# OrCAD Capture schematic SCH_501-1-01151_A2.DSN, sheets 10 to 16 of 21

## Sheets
10 P10_IMX CONTROL: size A3
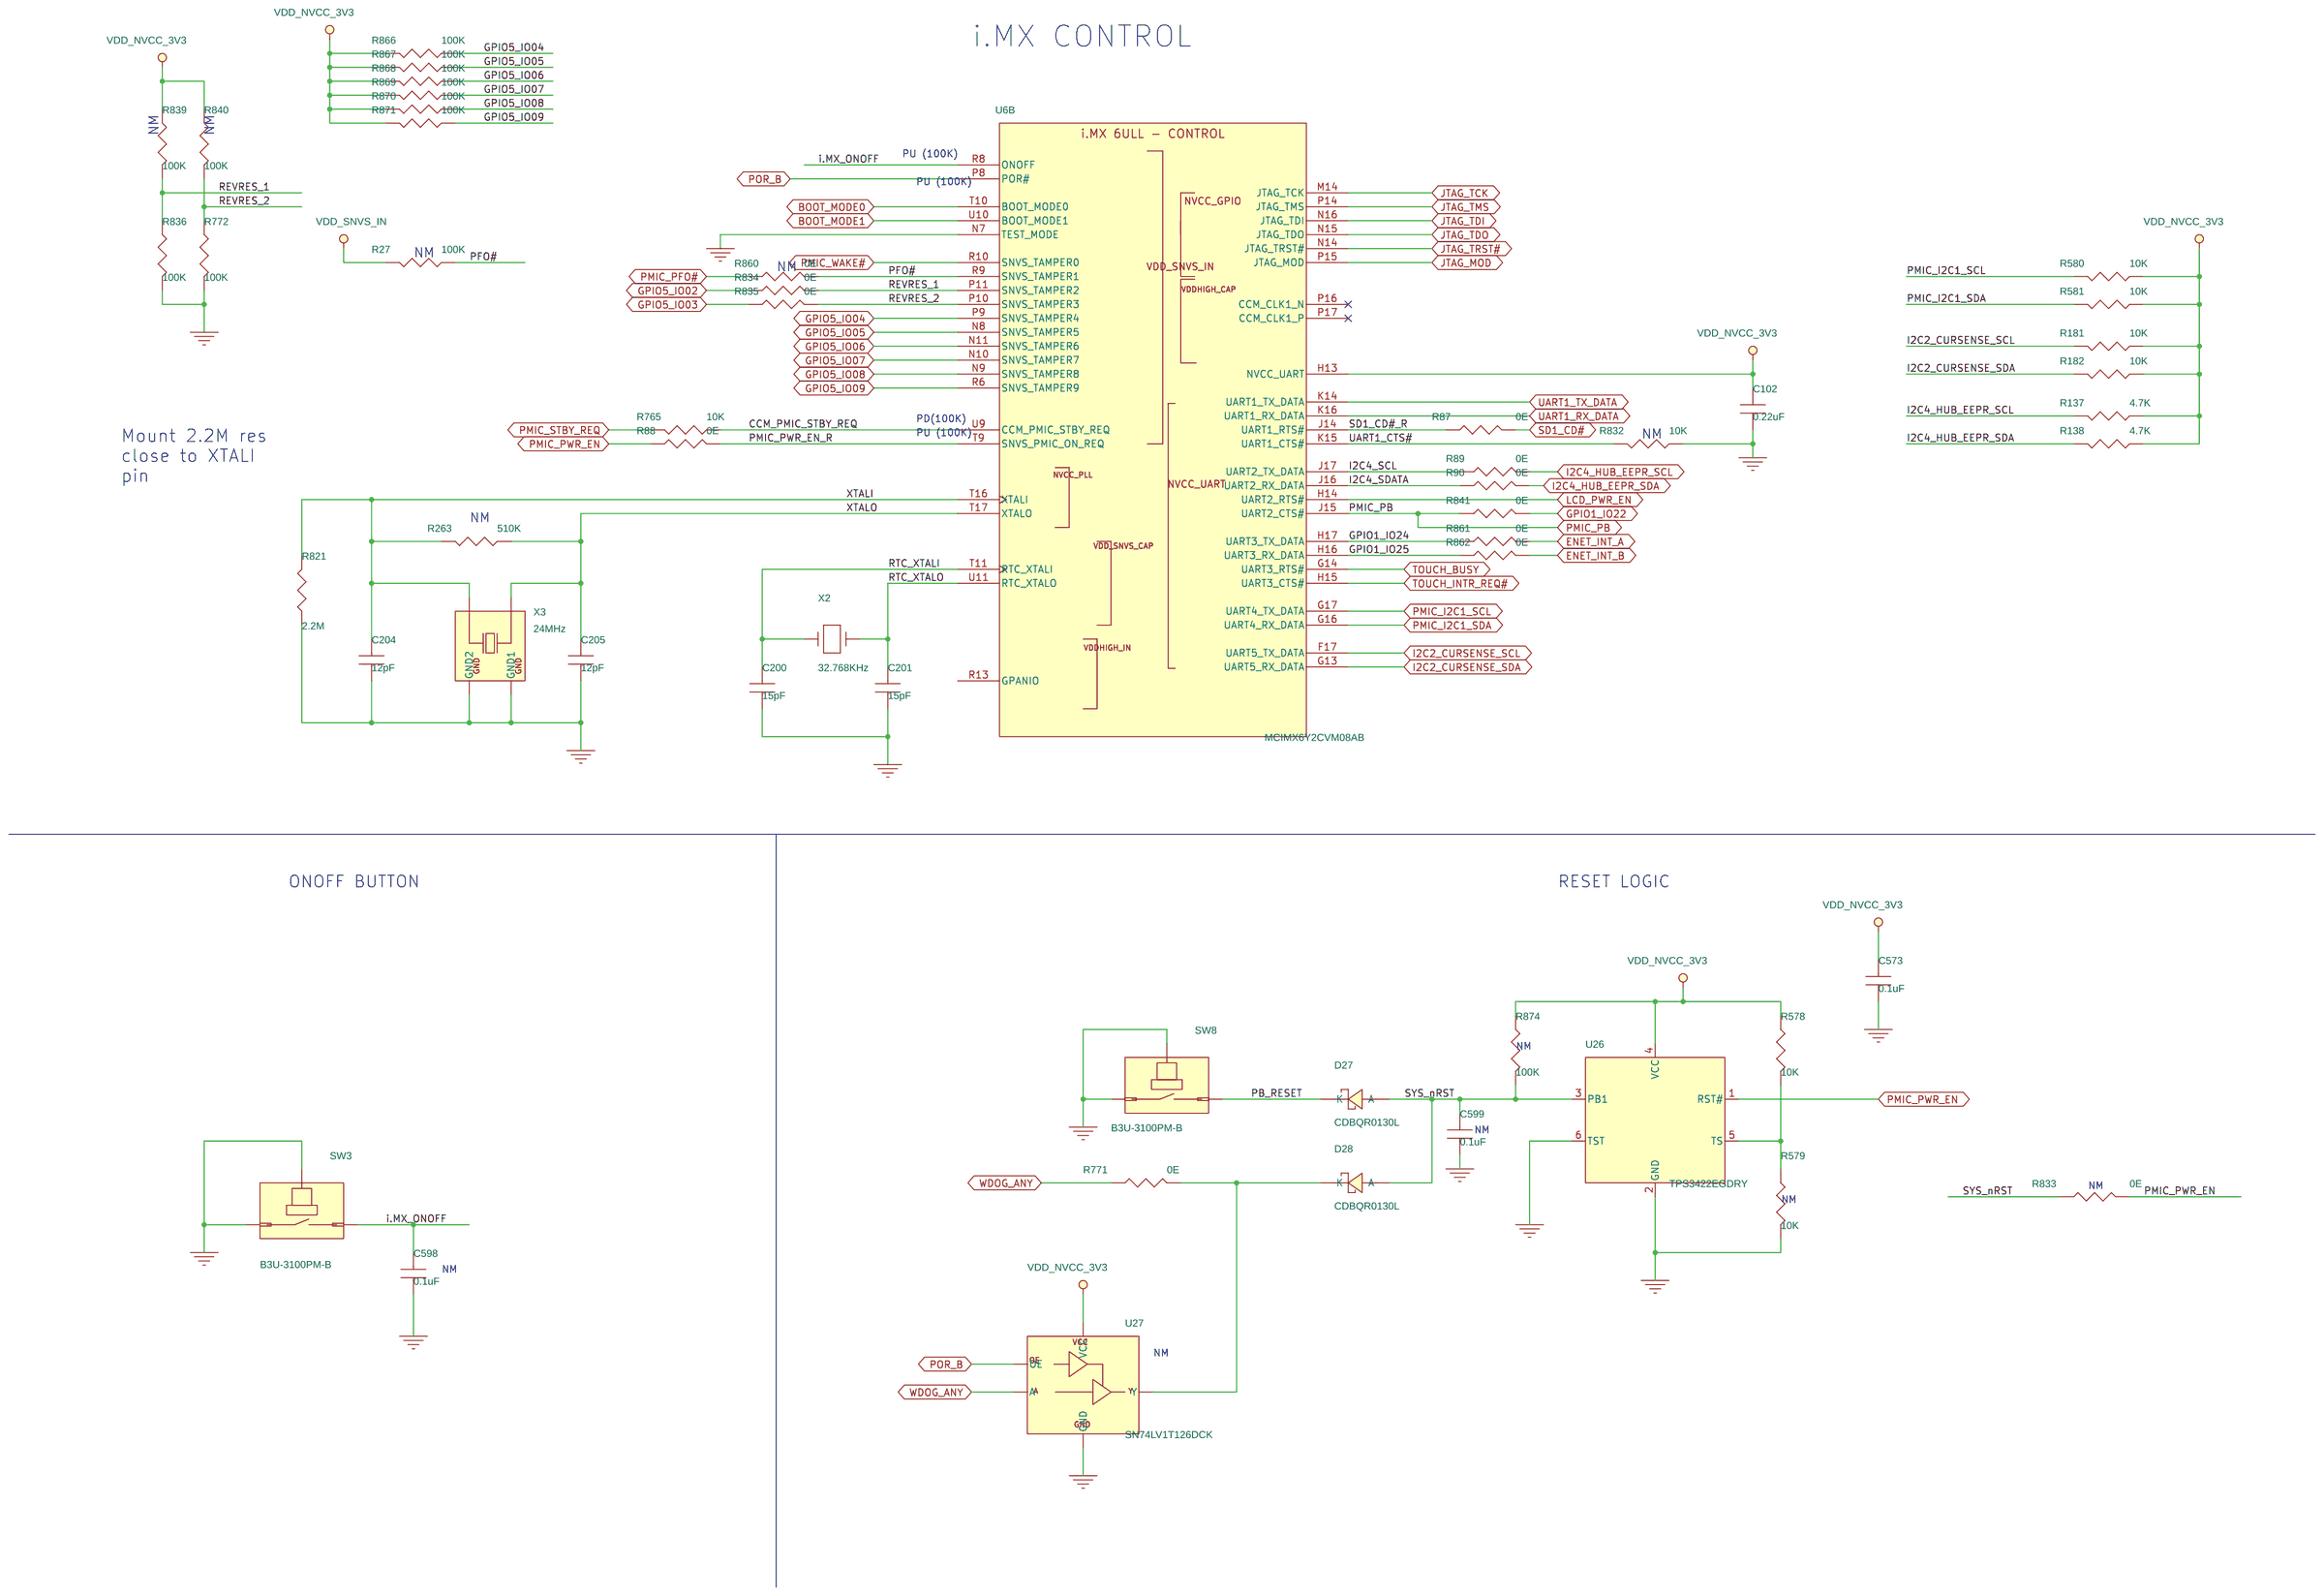
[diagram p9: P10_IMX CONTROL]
11 P11_eMMC: size A3
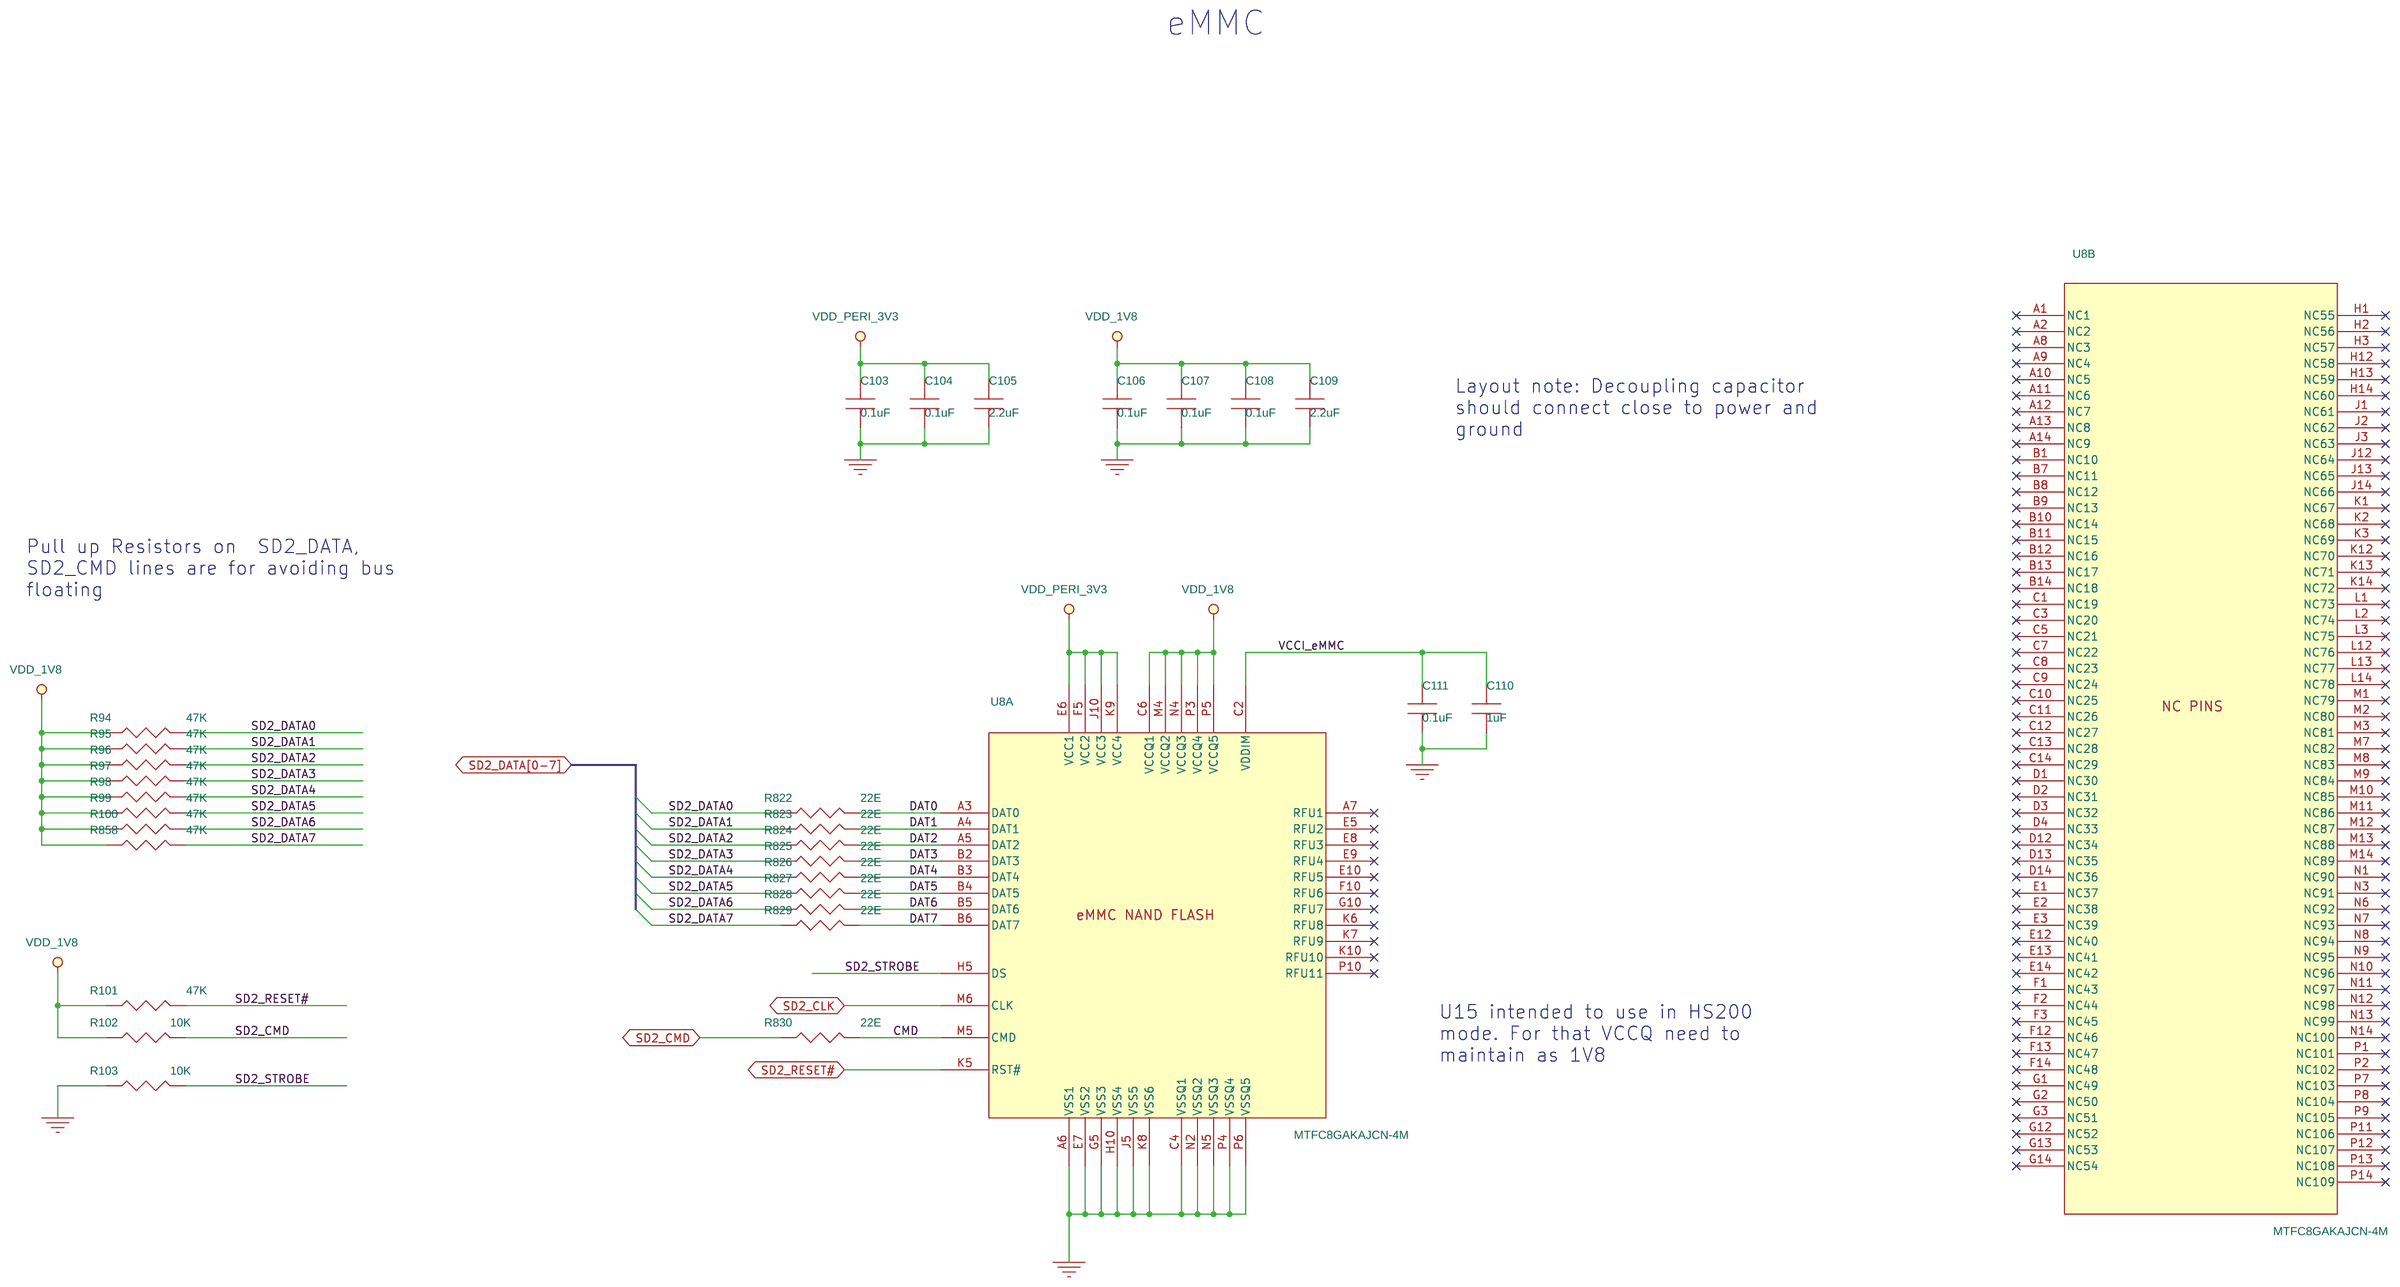
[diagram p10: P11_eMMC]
12 P12_NOR FLASH_SD CARD: size A3
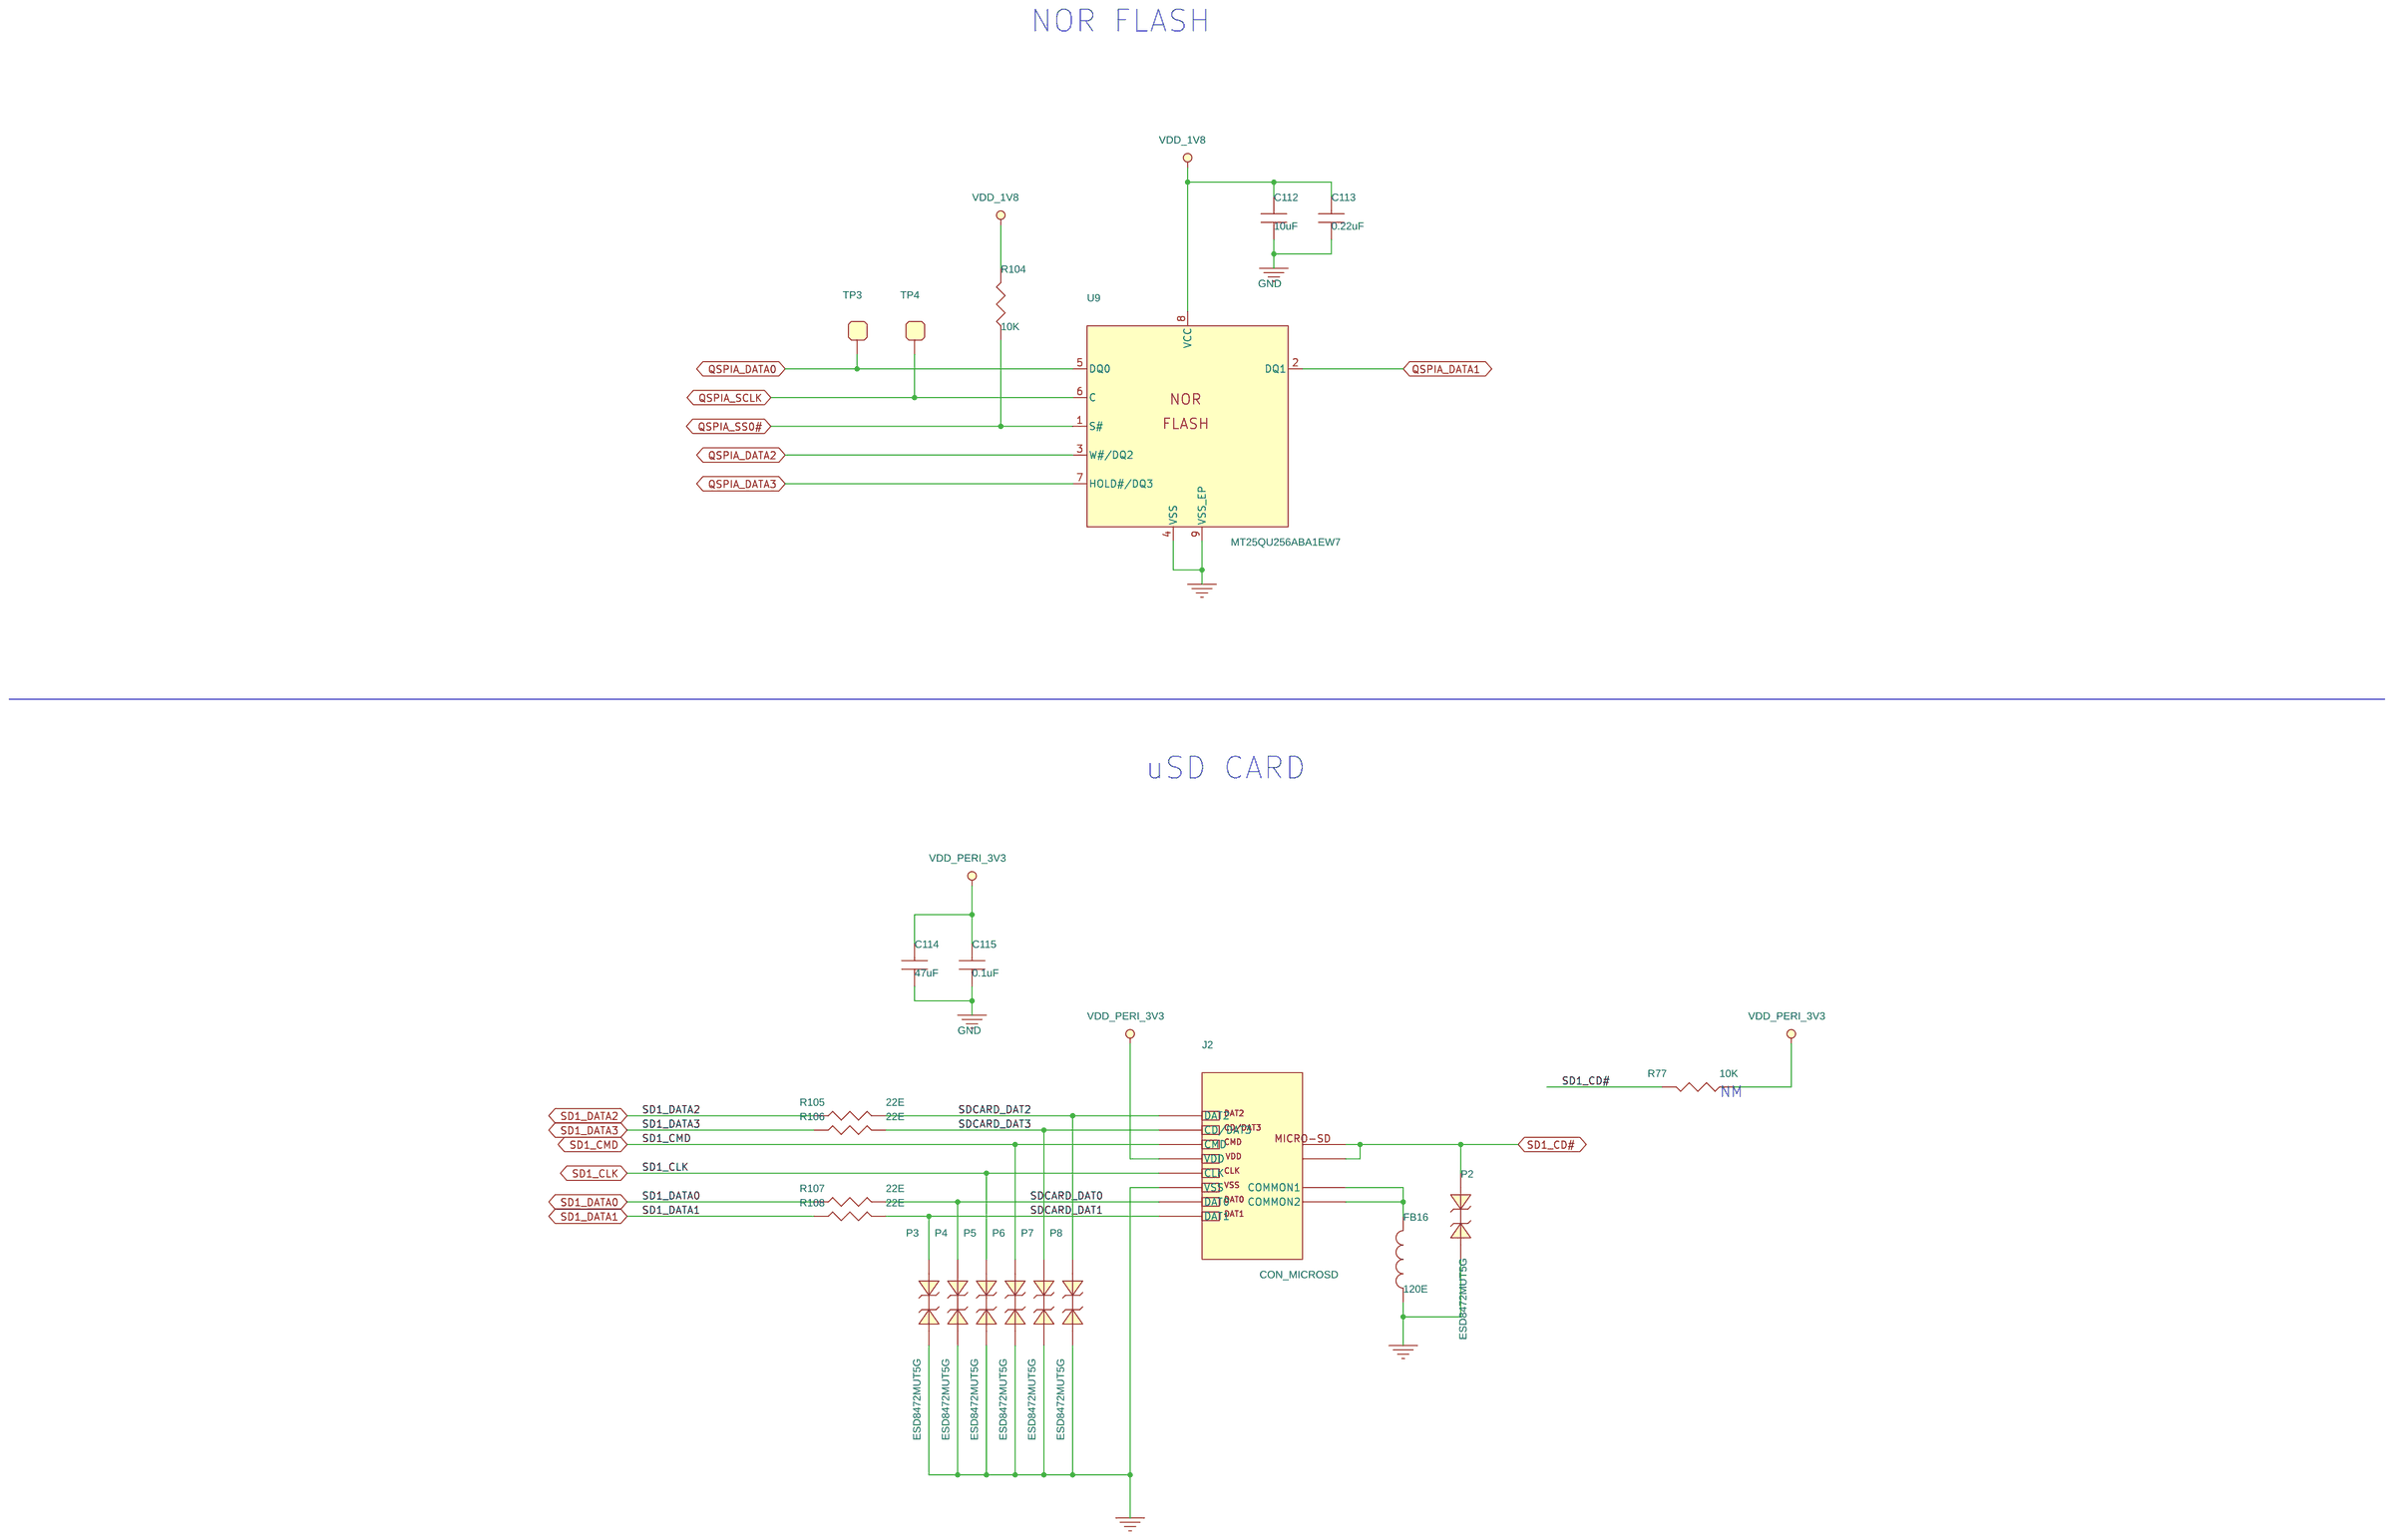
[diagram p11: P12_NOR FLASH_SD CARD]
13 P13_ETHERNET PHY: size A3
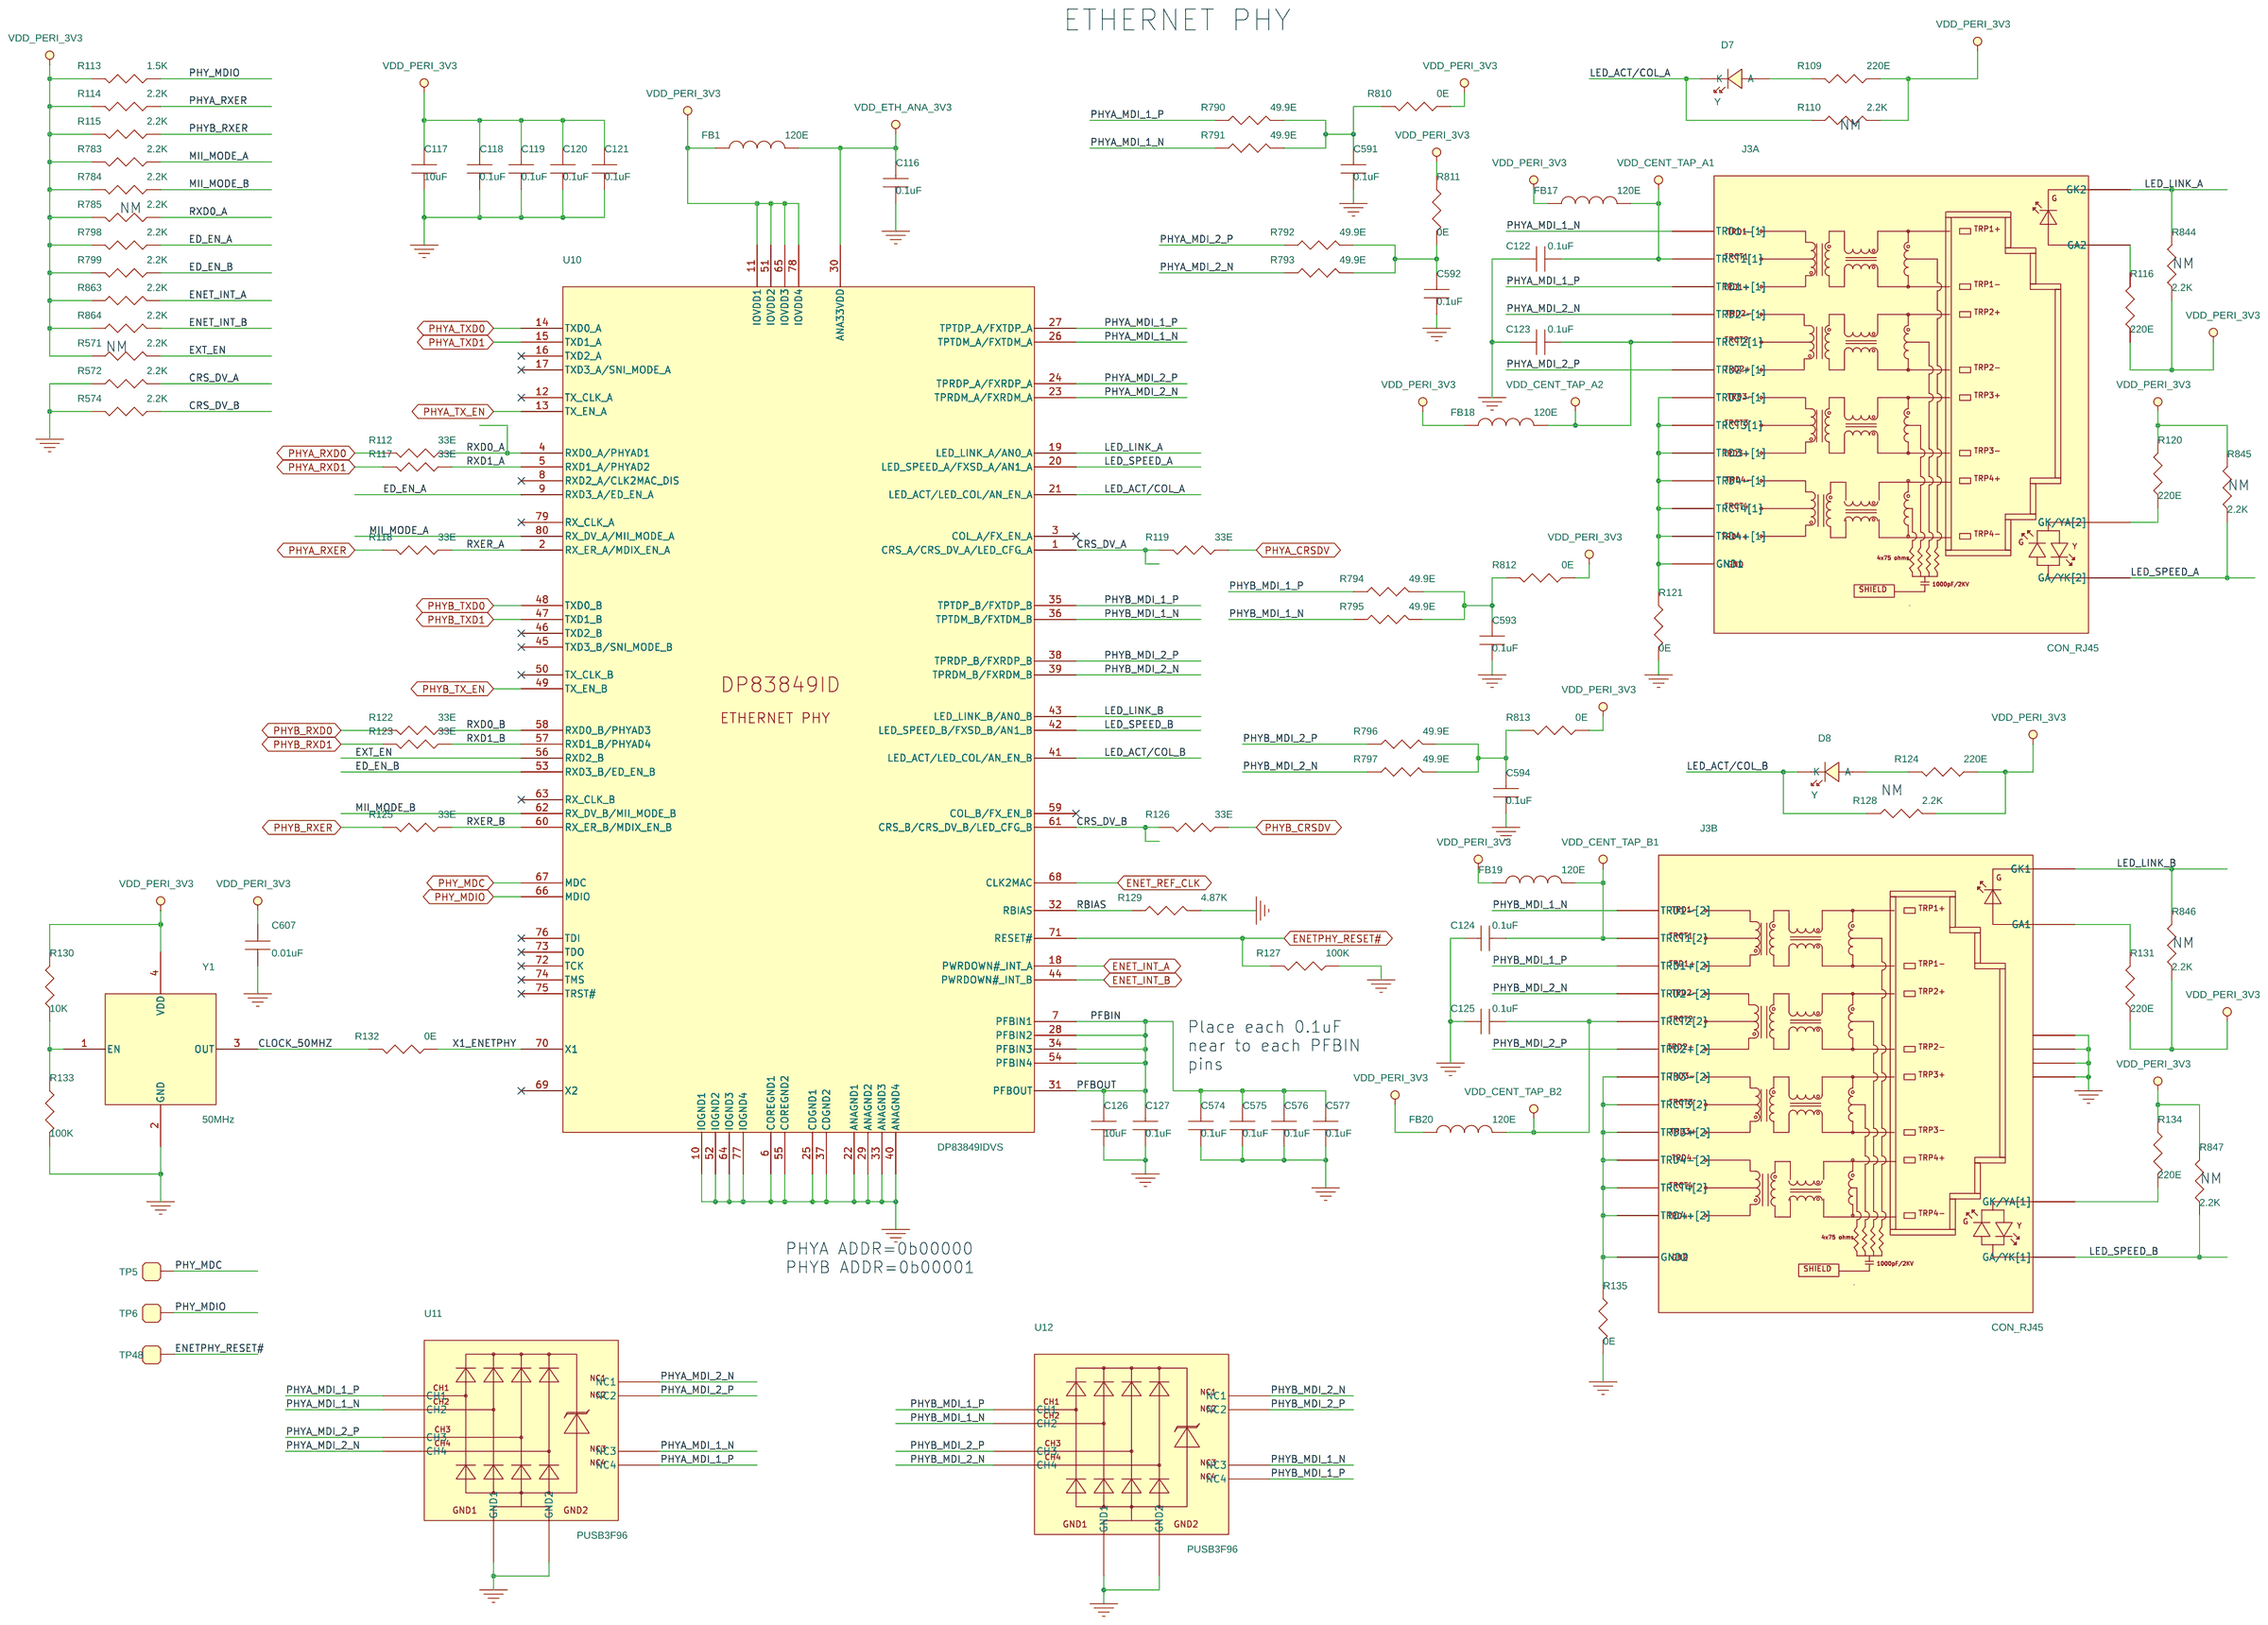
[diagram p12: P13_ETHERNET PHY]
14 P14_USB HUB: size A3
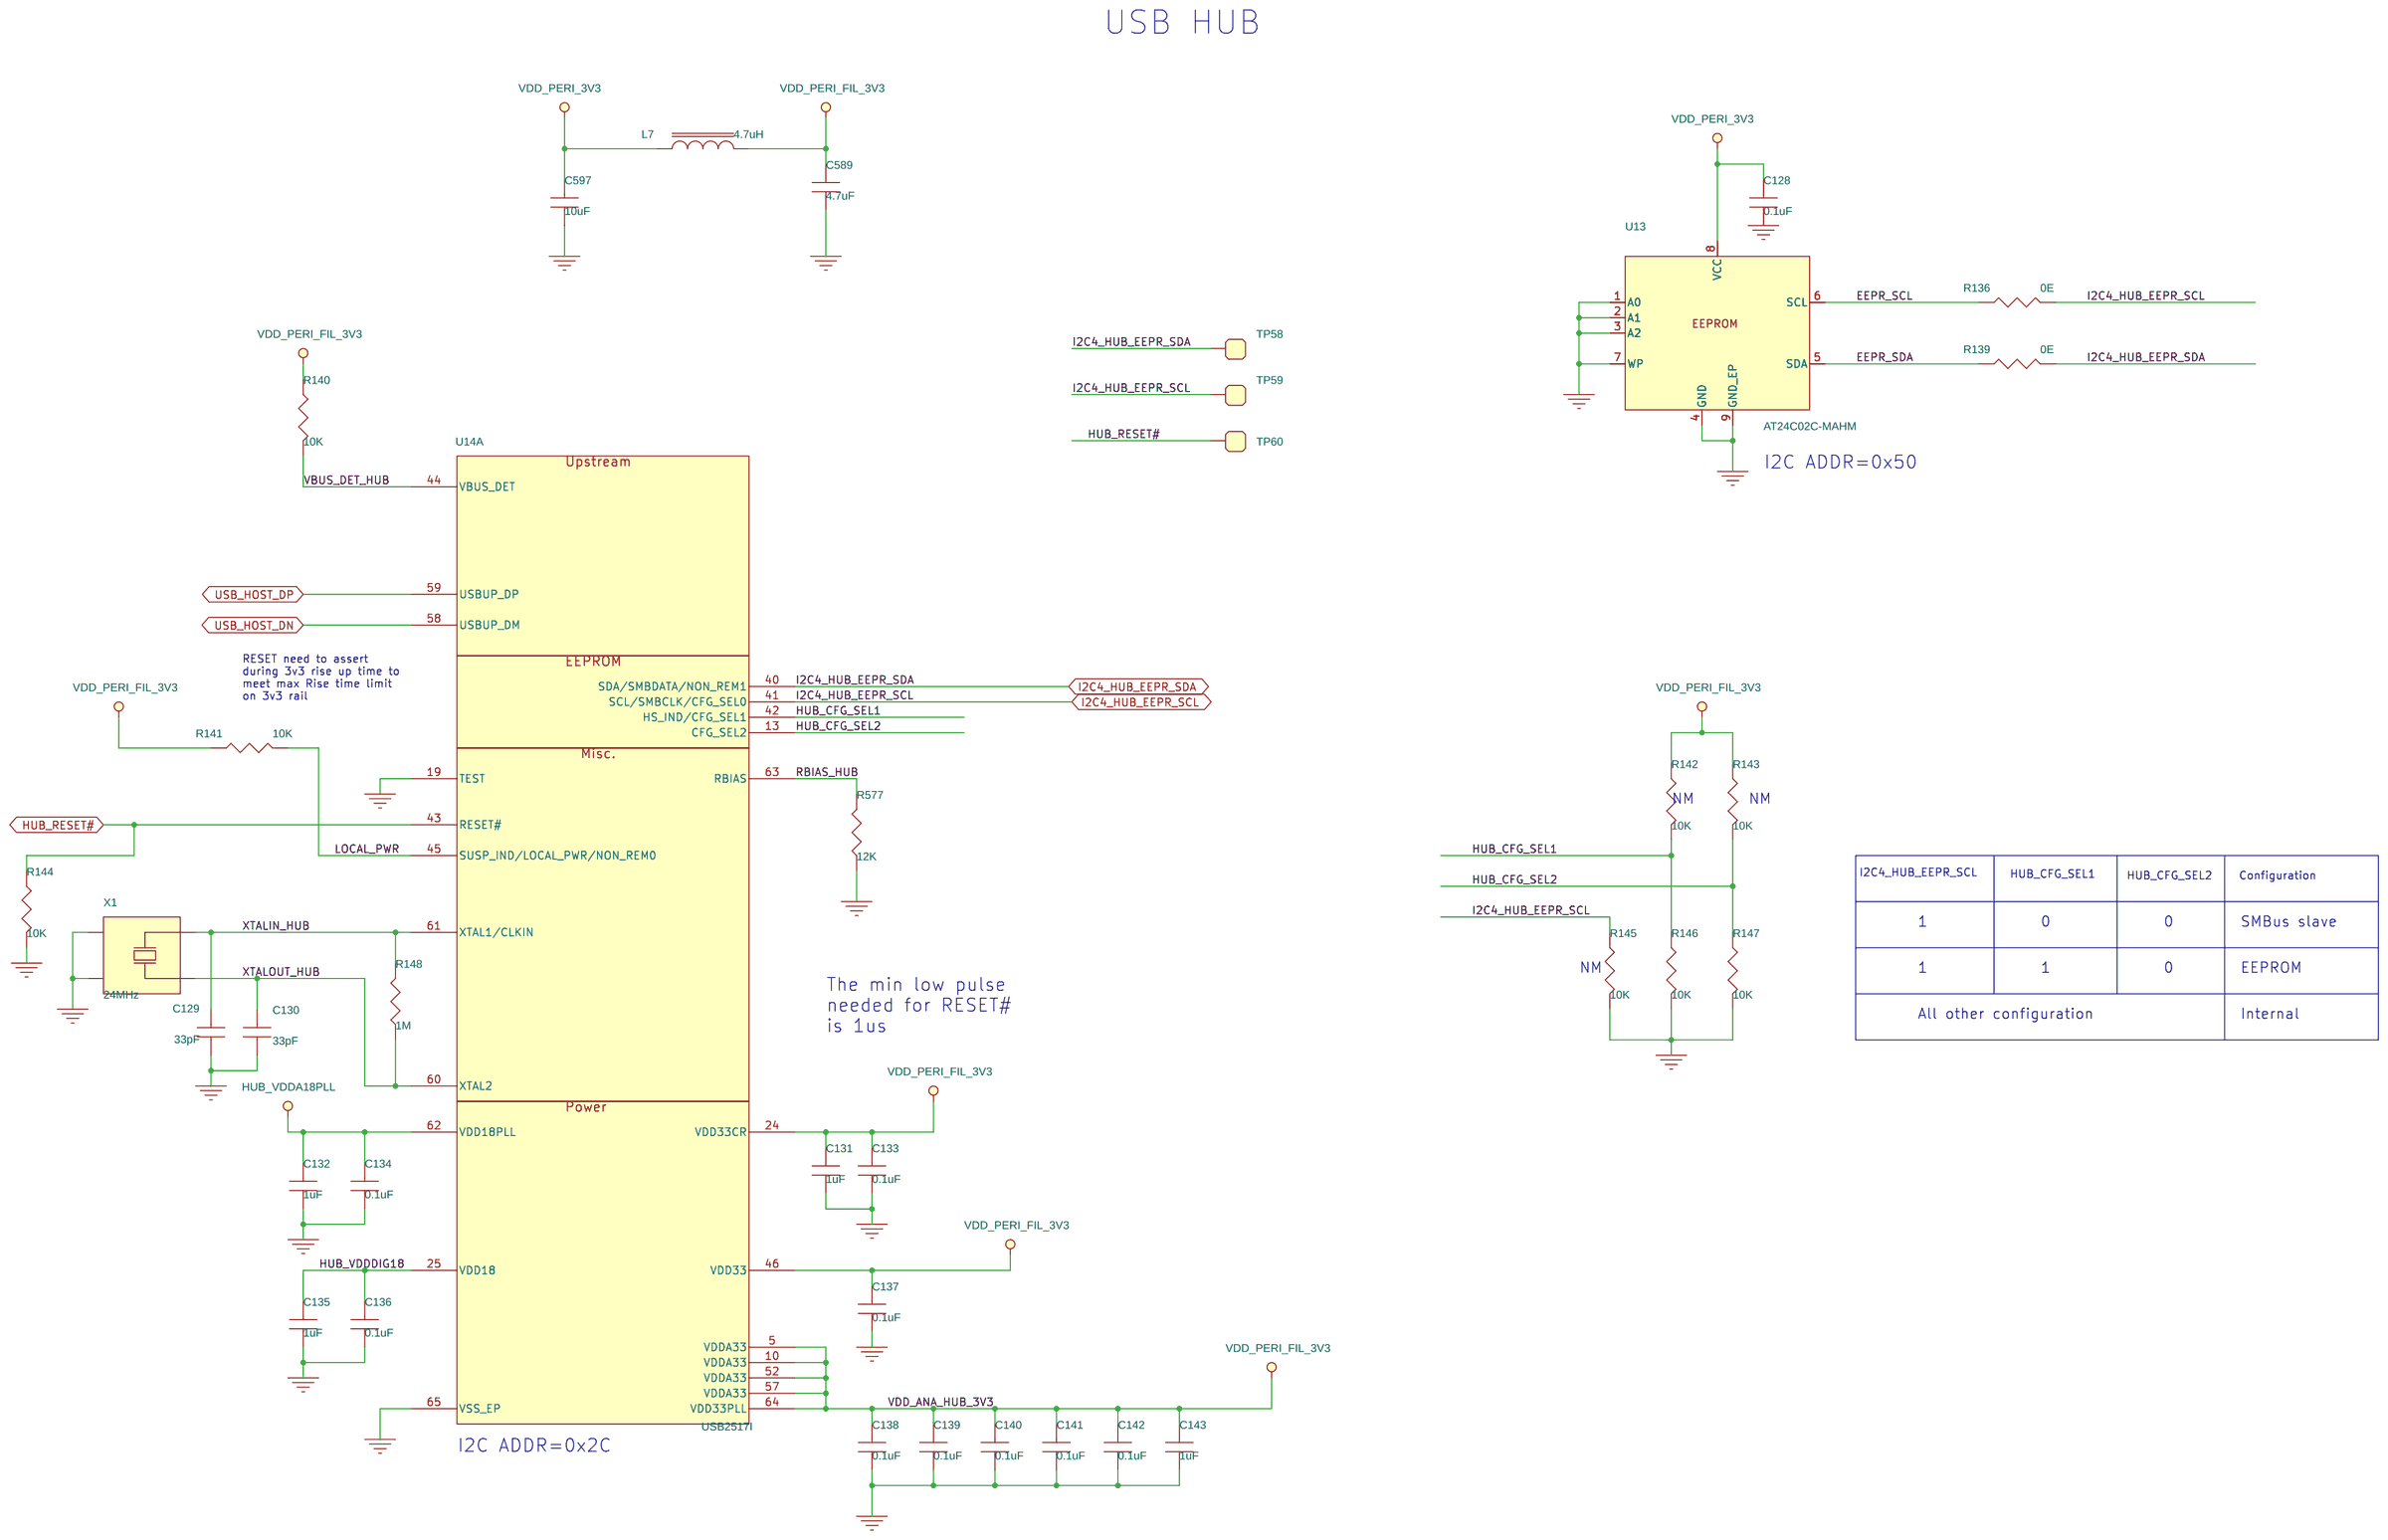
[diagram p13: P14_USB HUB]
15 P16_USB HUB CON: size A3
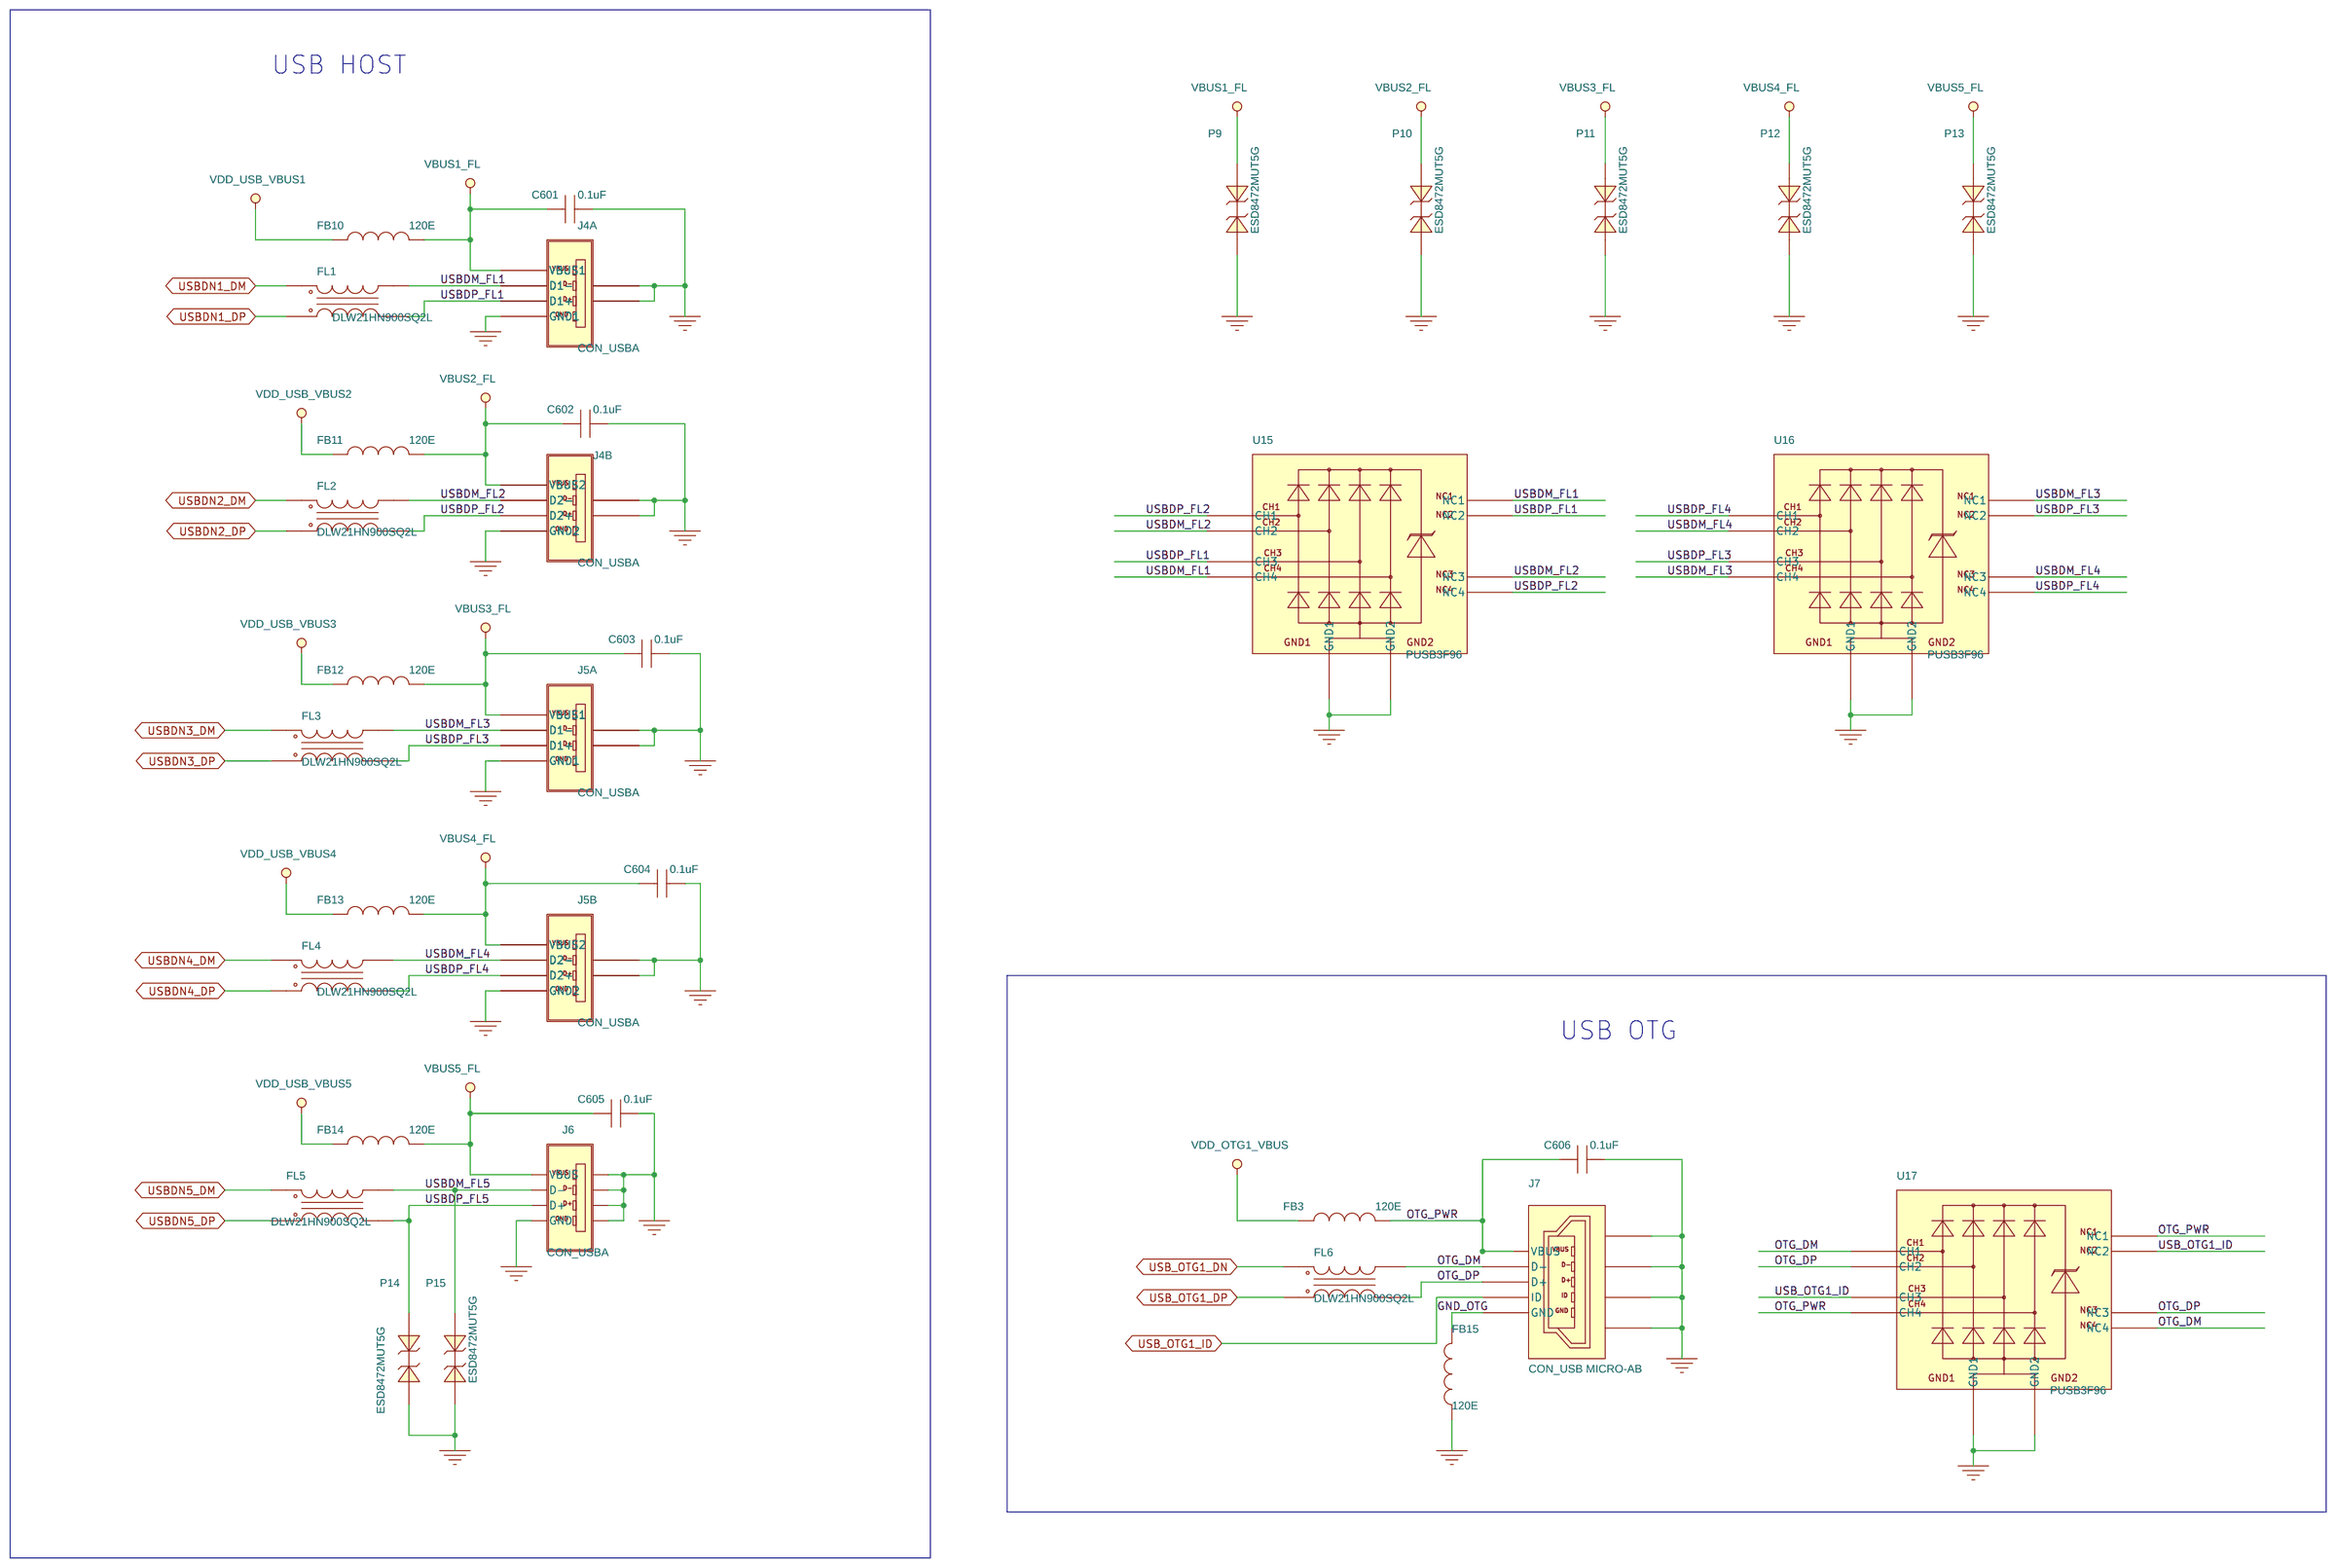
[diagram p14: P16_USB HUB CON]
16 P15_USB_OTG_HOST: size A3
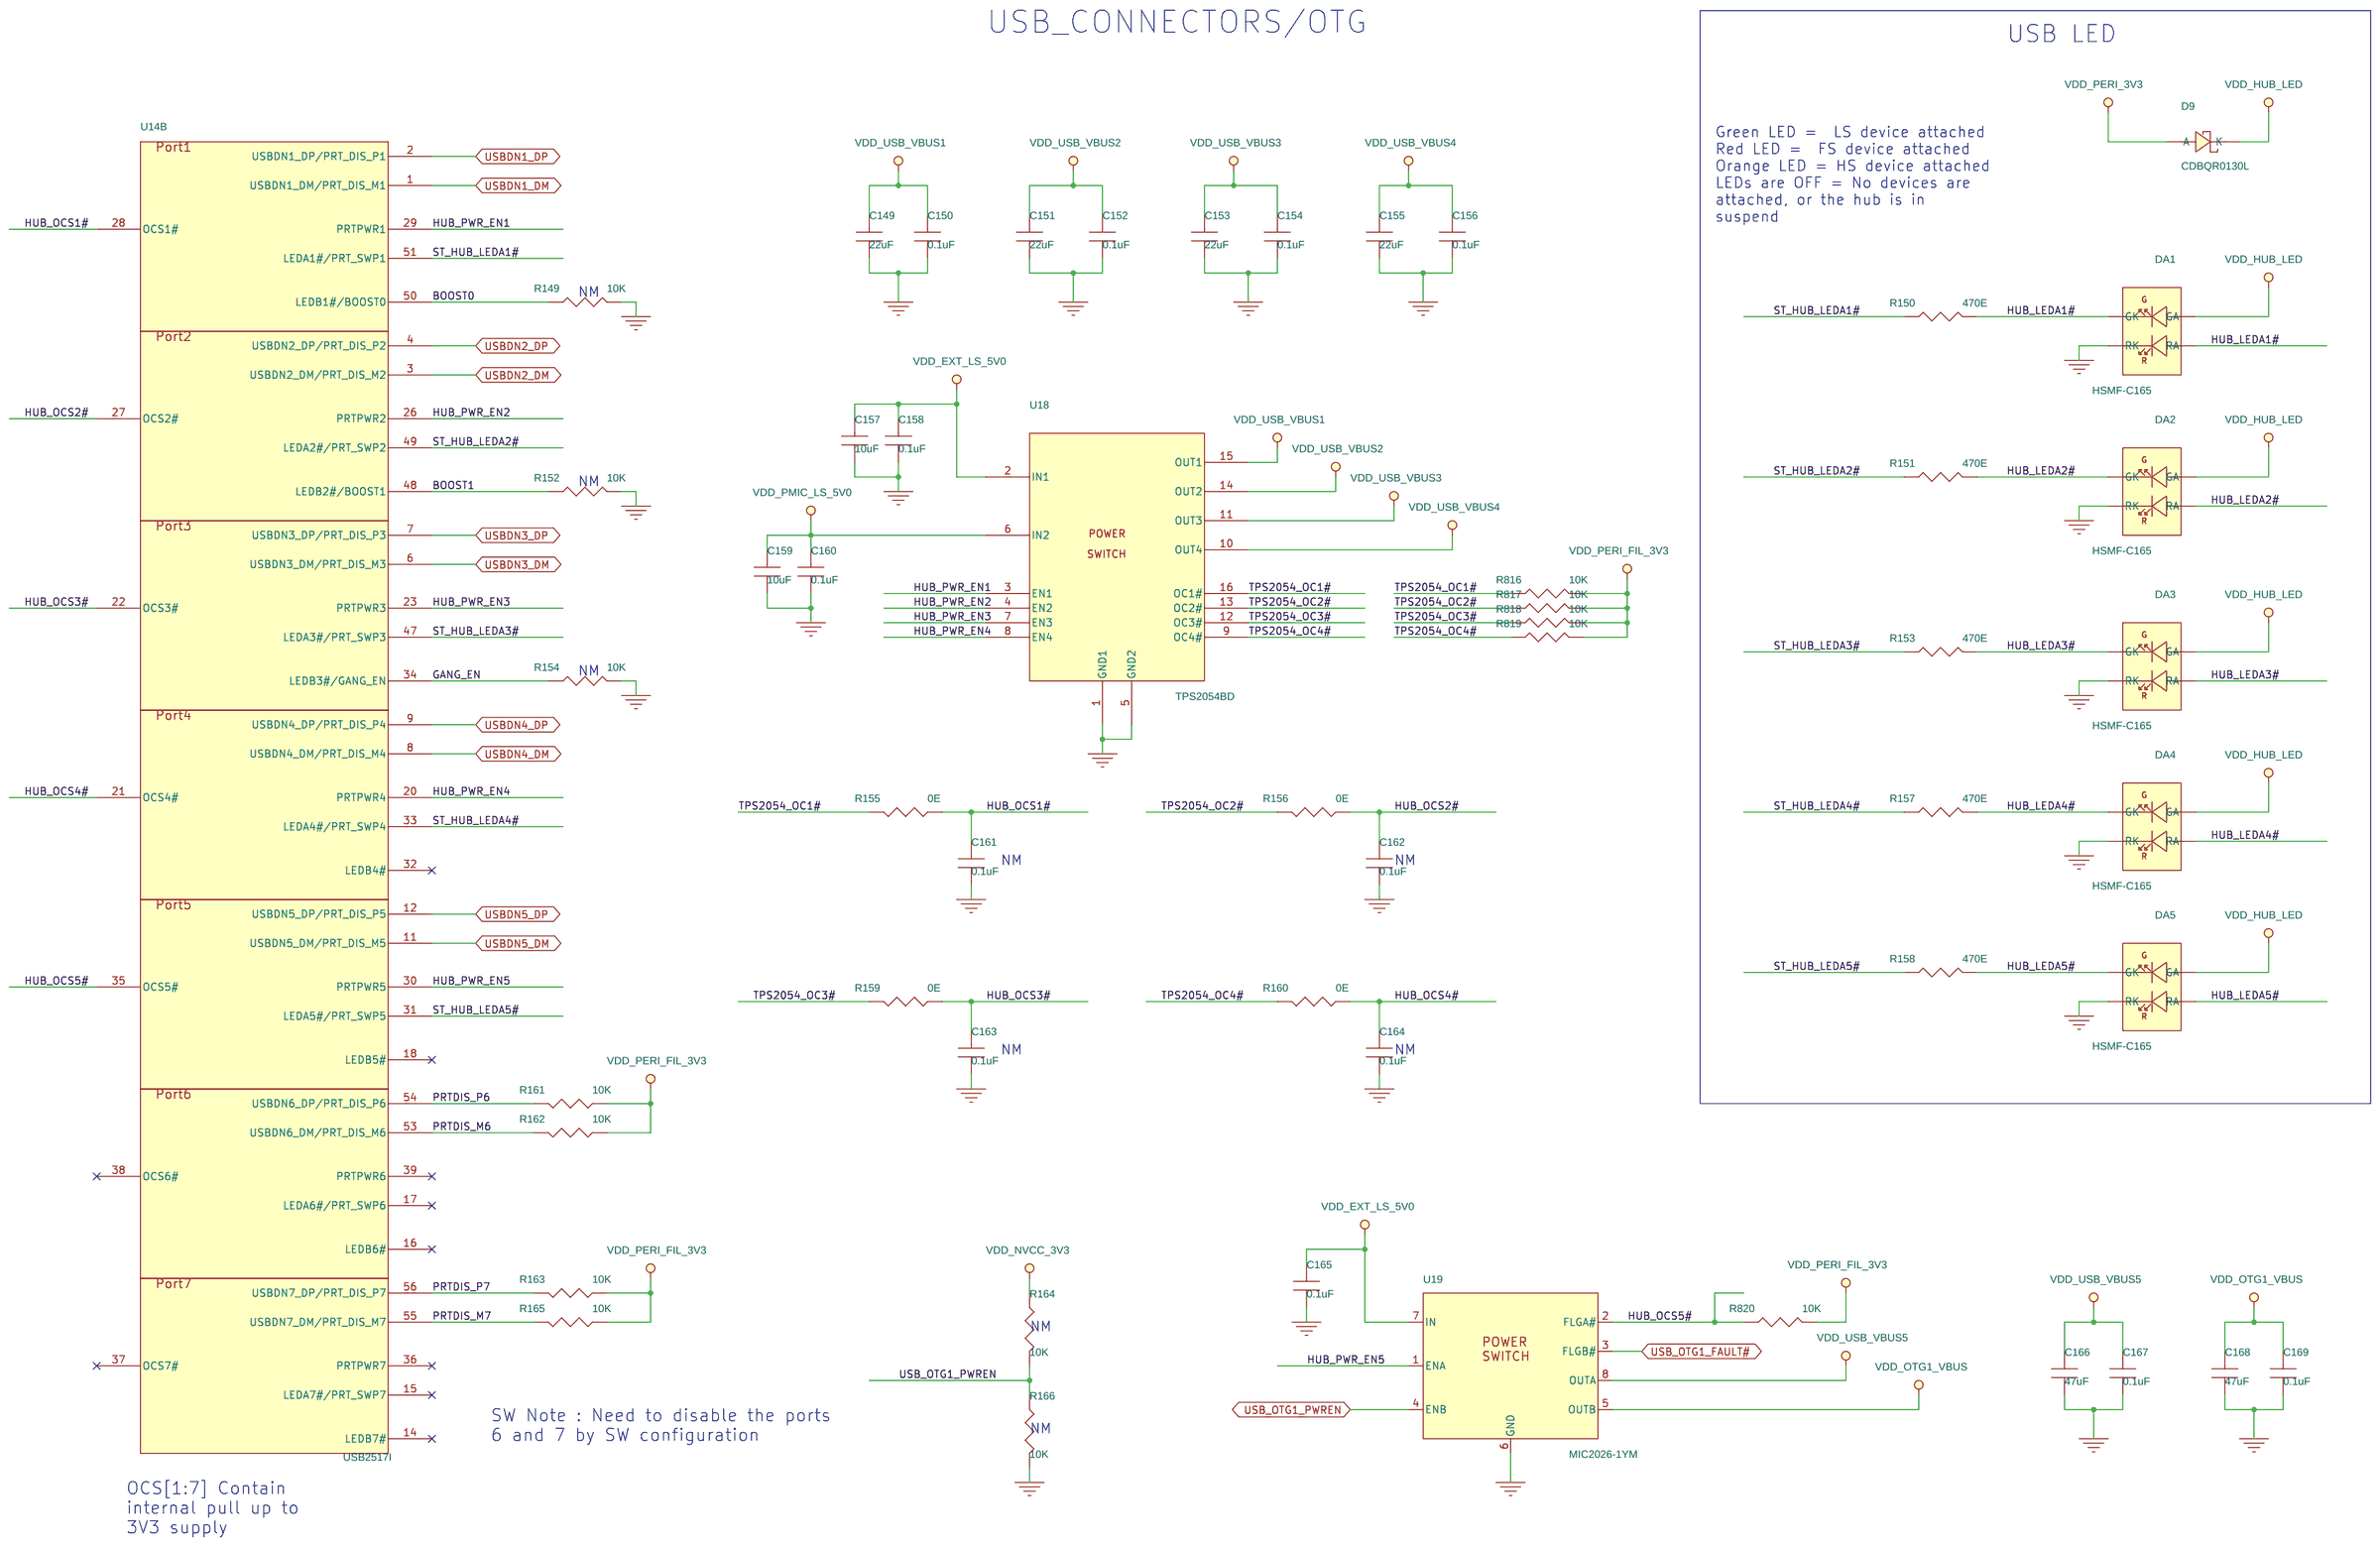
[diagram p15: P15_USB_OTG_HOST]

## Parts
sheet P06_IMX POWER
U6  MCIMX6Y2CVM08AB  [BGA289_0P8_14X14_A1]  (sections A,B,C,D,E,F,G,H,I,J,K)
sheet P10_IMX CONTROL
C102  0.22uF  [0402]
C200  15pF  [0402]
C201  15pF  [0402]
C204  12pF  [0201]
C205  12pF  [0201]
C573  0.1uF  [0402]
C598  0.1uF  [0402]
C599  0.1uF  [0402]
D27  CDBQR0130L  [DIO-0402]
D28  CDBQR0130L  [DIO-0402]
R27  100K  [0402]
R87  0E  [0402]
R88  0E  [0402]
R89  0E  [0402]
R90  0E  [0402]
R137  4.7K  [0402]
R138  4.7K  [0402]
R181  10K  [0402]
R182  10K  [0402]
R263  510K  [0402]
R578  10K  [0402]
R579  10K  [0402]
R580  10K  [0402]
R581  10K  [0402]
R765  10K  [0402]
R771  0E  [0402]
R772  100K  [0402]
R821  2.2M  [0402]
R832  10K  [0402]
R833  0E  [0402]
R834  0E  [0402]
R835  0E  [0402]
R836  100K  [0402]
R839  100K  [0402]
R840  100K  [0402]
R841  0E  [0402]
R860  0E  [0402]
R861  0E  [0402]
R862  0E  [0402]
R866  100K  [0402]
R867  100K  [0402]
R868  100K  [0402]
R869  100K  [0402]
R870  100K  [0402]
R871  100K  [0402]
R874  100K  [0402]
SW3  B3U-3100PM-B  [SW3_1P7_3X2P5_SM_RA_A1]
SW8  B3U-3100PM-B  [SW3_1P7_3X2P5_SM_RA_A1]
U26  TPS3422EGDRY  [SON6_0P5_1X1P45_A1]
U27  SN74LV1T126DCK  [SC70-5L_0P65_2X1P25_B_A1]
X2  32.768KHz  [XTAL2_2P5_3P2X1P5]
X3  24MHz  [XTAL4_1P6_3P2X2P5_A_A1]
sheet P11_eMMC
C103  0.1uF  [0402]
C104  0.1uF  [0402]
C105  2.2uF  [0402]
C106  0.1uF  [0402]
C107  0.1uF  [0402]
C108  0.1uF  [0402]
C109  2.2uF  [0402]
C110  1uF  [0402]
C111  0.1uF  [0402]
R94  47K  [0402]
R95  47K  [0402]
R96  47K  [0402]
R97  47K  [0402]
R98  47K  [0402]
R99  47K  [0402]
R100  47K  [0402]
R101  47K  [0402]
R102  10K  [0402]
R103  10K  [0402]
R822  22E  [0402]
R823  22E  [0402]
R824  22E  [0402]
R825  22E  [0402]
R826  22E  [0402]
R827  22E  [0402]
R828  22E  [0402]
R829  22E  [0402]
R830  22E  [0402]
R858  47K  [0402]
U8  MTFC8GAKAJCN-4M  [BGA153_0P5_11P5X13_C_A1]  (sections A,B)
sheet P12_NOR FLASH_SD CARD
C112  10uF  [0402]
C113  0.22uF  [0402]
C114  47uF  [0805_B_A1]
C115  0.1uF  [0402]
FB16  120E  [0402]
J2  CON_MICROSD  [CON_USD_1X1F_12L_1P1_SM_RA]
P2  ESD8472MUT5G  [DIO-0201]
P3  ESD8472MUT5G  [DIO-0201]
P4  ESD8472MUT5G  [DIO-0201]
P5  ESD8472MUT5G  [DIO-0201]
P6  ESD8472MUT5G  [DIO-0201]
P7  ESD8472MUT5G  [DIO-0201]
P8  ESD8472MUT5G  [DIO-0201]
R77  10K  [0402]
R104  10K  [0402]
R105  22E  [0402]
R106  22E  [0402]
R107  22E  [0402]
R108  22E  [0402]
TP3  SMD  [TP35_SMD]
TP4  SMD  [TP35_SMD]
U9  MT25QU256ABA1EW7  [WPDFN8_1P27_6X5_EP_A1]
sheet P13_ETHERNET PHY
C116  0.1uF  [0402]
C117  10uF  [0402]
C118  0.1uF  [0402]
C119  0.1uF  [0402]
C120  0.1uF  [0402]
C121  0.1uF  [0402]
C122  0.1uF  [0402]
C123  0.1uF  [0402]
C124  0.1uF  [0402]
C125  0.1uF  [0402]
C126  10uF  [0402]
C127  0.1uF  [0402]
C574  0.1uF  [0402]
C575  0.1uF  [0402]
C576  0.1uF  [0402]
C577  0.1uF  [0402]
C591  0.1uF  [0402]
C592  0.1uF  [0402]
C593  0.1uF  [0402]
C594  0.1uF  [0402]
C607  0.01uF  [0402]
D7  Y  [LED-0603_C_A1]
D8  Y  [LED-0603_C_A1]
FB1  120E  [0402]
FB17  120E  [0402]
FB18  120E  [0402]
FB19  120E  [0402]
FB20  120E  [0402]
J3  CON_RJ45  [CON_RJ45_2X1_2P01_TH_RA_A1]  (sections A,B)
R109  220E  [0402]
R110  2.2K  [0402]
R112  33E  [0402]
R113  1.5K  [0402]
R114  2.2K  [0402]
R115  2.2K  [0402]
R116  220E  [0402]
R117  33E  [0402]
R118  33E  [0402]
R119  33E  [0402]
R120  220E  [0402]
R121  0E  [0402]
R122  33E  [0402]
R123  33E  [0402]
R124  220E  [0402]
R125  33E  [0402]
R126  33E  [0402]
R127  100K  [0402]
R128  2.2K  [0402]
R129  4.87K  [0402]
R130  10K  [0402]
R131  220E  [0402]
R132  0E  [0402]
R133  100K  [0402]
R134  220E  [0402]
R135  0E  [0402]
R571  2.2K  [0402]
R572  2.2K  [0402]
R574  2.2K  [0402]
R783  2.2K  [0402]
R784  2.2K  [0402]
R785  2.2K  [0402]
R790  49.9E  [0402]
R791  49.9E  [0402]
R792  49.9E  [0402]
R793  49.9E  [0402]
R794  49.9E  [0402]
R795  49.9E  [0402]
R796  49.9E  [0402]
R797  49.9E  [0402]
R798  2.2K  [0402]
R799  2.2K  [0402]
R810  0E  [0402]
R811  0E  [0402]
R812  0E  [0402]
R813  0E  [0402]
R844  2.2K  [0402]
R845  2.2K  [0402]
R846  2.2K  [0402]
R847  2.2K  [0402]
R863  2.2K  [0402]
R864  2.2K  [0402]
TP5  SMD  [TP40_SMD]
TP6  SMD  [TP40_SMD]
TP48  SMD  [TP40_SMD]
U10  DP83849IDVS  [QFP80_0P5_12X12]
U11  PUSB3F96  [DFN2510A-10L_0P5_2P5X1]
U12  PUSB3F96  [DFN2510A-10L_0P5_2P5X1]
Y1  50MHz  [OSC4_2P2_5P2X3P4]
sheet P14_USB HUB
C128  0.1uF  [0402]
C129  33pF  [0402]
C130  33pF  [0402]
C131  1uF  [0402]
C132  1uF  [0402]
C133  0.1uF  [0402]
C134  0.1uF  [0402]
C135  1uF  [0402]
C136  0.1uF  [0402]
C137  0.1uF  [0402]
C138  0.1uF  [0402]
C139  0.1uF  [0402]
C140  0.1uF  [0402]
C141  0.1uF  [0402]
C142  0.1uF  [0402]
C143  1uF  [0402]
C589  4.7uF  [0603]
C597  10uF  [0402]
L7  4.7uH  [IND-2520_1_A1]
R136  0E  [0402]
R139  0E  [0402]
R140  10K  [0402]
R141  10K  [0402]
R142  10K  [0402]
R143  10K  [0402]
R144  10K  [0402]
R145  10K  [0402]
R146  10K  [0402]
R147  10K  [0402]
R148  1M  [0402]
R577  12K  [0402]
TP58  SMD  [TP40_SMD]
TP59  SMD  [TP40_SMD]
TP60  SMD  [TP40_SMD]
U13  AT24C02C-MAHM  [UDFN8_0P5_3X2_EP_A_A1]
U14  USB2517I  [QFN64_0P5_9X9_EP_Y_A1]  (sections A,B)
X1  24MHz  [XTAL4_1P55_3P2X2P5]
sheet P15_USB_OTG_HOST
C149  22uF  [0603]
C150  0.1uF  [0402]
C151  22uF  [0603]
C152  0.1uF  [0402]
C153  22uF  [0603]
C154  0.1uF  [0402]
C155  22uF  [0603]
C156  0.1uF  [0402]
C157  10uF  [0402]
C158  0.1uF  [0402]
C159  10uF  [0402]
C160  0.1uF  [0402]
C161  0.1uF  [0402]
C162  0.1uF  [0402]
C163  0.1uF  [0402]
C164  0.1uF  [0402]
C165  0.1uF  [0402]
C166  47uF  [0805_B_A1]
C167  0.1uF  [0402]
C168  47uF  [0805_B_A1]
C169  0.1uF  [0402]
D9  CDBQR0130L  [DIO-0402]
DA1  HSMF-C165  [LED4_0P7_1P6X0P8]
DA2  HSMF-C165  [LED4_0P7_1P6X0P8]
DA3  HSMF-C165  [LED4_0P7_1P6X0P8]
DA4  HSMF-C165  [LED4_0P7_1P6X0P8]
DA5  HSMF-C165  [LED4_0P7_1P6X0P8]
R149  10K  [0402]
R150  470E  [0402]
R151  470E  [0402]
R152  10K  [0402]
R153  470E  [0402]
R154  10K  [0402]
R155  0E  [0402]
R156  0E  [0402]
R157  470E  [0402]
R158  470E  [0402]
R159  0E  [0402]
R160  0E  [0402]
R161  10K  [0402]
R162  10K  [0402]
R163  10K  [0402]
R164  10K  [0402]
R165  10K  [0402]
R166  10K  [0402]
R816  10K  [0402]
R817  10K  [0402]
R818  10K  [0402]
R819  10K  [0402]
R820  10K  [0402]
U18  TPS2054BD  [SOIC16_1P27_3P9X9P9_A1]
U19  MIC2026-1YM  [SOIC8_1P27_4X5]
sheet P16_USB HUB CON
C601  0.1uF  [0402]
C602  0.1uF  [0402]
C603  0.1uF  [0402]
C604  0.1uF  [0402]
C605  0.1uF  [0402]
C606  0.1uF  [0402]
FB3  120E  [0402]
FB10  120E  [0402]
FB11  120E  [0402]
FB12  120E  [0402]
FB13  120E  [0402]
FB14  120E  [0402]
FB15  120E  [0402]
FL1  DLW21HN900SQ2L  [CM_CHK4_0P8_2X1P2]
FL2  DLW21HN900SQ2L  [CM_CHK4_0P8_2X1P2]
FL3  DLW21HN900SQ2L  [CM_CHK4_0P8_2X1P2]
FL4  DLW21HN900SQ2L  [CM_CHK4_0P8_2X1P2]
FL5  DLW21HN900SQ2L  [CM_CHK4_0P8_2X1P2]
FL6  DLW21HN900SQ2L  [CM_CHK4_0P8_2X1P2]
J4  CON_USBA  [CON_USB-A_2X1F_2_TH_RA_A1]  (sections A,B)
J5  CON_USBA  [CON_USB-A_2X1F_2_TH_RA_A1]  (sections A,B)
J6  CON_USBA  [CON_USB-A_1X1F_2_TH_RA_D_A1]
J7  CON_USB MICRO-AB  [CON_USB_5F_0P65_SM_RA_A2]
P9  ESD8472MUT5G  [DIO-0201]
P10  ESD8472MUT5G  [DIO-0201]
P11  ESD8472MUT5G  [DIO-0201]
P12  ESD8472MUT5G  [DIO-0201]
P13  ESD8472MUT5G  [DIO-0201]
P14  ESD8472MUT5G  [DIO-0201]
P15  ESD8472MUT5G  [DIO-0201]
U15  PUSB3F96  [DFN2510A-10L_0P5_2P5X1]
U16  PUSB3F96  [DFN2510A-10L_0P5_2P5X1]
U17  PUSB3F96  [DFN2510A-10L_0P5_2P5X1]

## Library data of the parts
U6 = IC_IMX6ULL_BGA-289P_CST_A1: IC, uP, iMX6ULL, ARM Cortex-A7 Application Processor, 792MHz, MAPBGA-289; EN: 301-1-00454; KEY Number: 301-1-00454@1; Mfg: NXP SEMICONDUCTORS; Temperature: -40°C to +105°C
C102 C113 = CAP_NP: Cap, Cer-X5R, 0.22uF, 10V, 10%, 0402; EN: 102-1-00210; FPLIST: 0402,0402_CIR; KEY Number: 102-1-00210@1; Mfg: MURATA MANUFACTURING CO,LTD; Mfg Part No: GRM155R61A224KE19D; Temperature: -55°C to +85°C
C200 C201 = CAP_NP: Cap, Cer-NPO, 15pF, 50V, 1%, 0402; EN: 102-1-00760; KEY Number: 102-1-00760@2; Mfg: MURATA MANUFACTURING CO,LTD; Mfg Part No: GRM1555C1H150FA01*; Temperature: -55°C to +125°C
C204 C205 = CAP_NP: Cap, Cer-NPO, 12pF, 25V, 5%, 0201; EN: 102-1-02047; KEY Number: 102-1-02047@1; Mfg: MURATA MANUFACTURING CO,LTD; Mfg Part No: GRM0335C1E120JA01*; Temperature: -55°C to +125°C
C103 C104 C106-C108 C111 C115 C116 C118-C125 C127 C128 C133 C134 C136-C142 C150 C152 C154 C156 C158 C160-C165 C167 C169 C573-C577 C591-C594 C598 C599 C601-C606 = CAP_NP: Cap, Cer-X7R, 0.1uF, 16V, 10%, 0402; EN: 102-1-01629; KEY Number: 102-1-01629@1; Mfg: WALSIN TECHNOLOGY CORP.; Mfg Part No: 0402B104K160CT; Temperature: -55°C to +125°C
D9 D27 D28 = DIODE_SCH: Diode, Schottky, 0.1A, 30V, 0.125W, 0402; EN: 106-2-00083; KEY Number: 106-2-00083@1; Mfg: COMCHIP TECHNOLOGY; Mfg Part No: CDBQR0130L-HF; Temperature: -40°C to +125°C
R27 R127 R133 R772 R836 R839 R840 R866-R871 R874 = RES_v2: Res, Chip, 100K, 1/16W, 1%, 0402; EN: 101-1-00485; KEY Number: 101-1-00485@3; Mfg: WALSIN TECHNOLOGY CORP.; Mfg Part No: WR04X1003FTL; Temperature: -55°C to +155°C
R87-R90 R121 R132 R135 R136 R139 R155 R156 R159 R160 R771 R810-R813 R833-R835 R841 R860-R862 = RES_v2: Res, Chip, 0E, 1/16W, 1.5A, AEC-Q200, 0402; EN: 101-1-00001; KEY Number: 101-1-00001@2; Mfg: VISHAY; Mfg Part No: CRCW04020000Z0ED; Temperature: -55°C to +155°C
R137 R138 = RES_v2: Res, Chip, 4.7K, 1/16W, 1%, 0402; EN: 101-1-03446; KEY Number: 101-1-03446@2; Mfg: WALSIN TECHNOLOGY CORP.; Mfg Part No: WR04X4701FTL; Temperature: -55°C to +155°C
R77 R102-R104 R130 R140-R147 R149 R152 R154 R161-R166 R181 R182 R578-R581 R765 R816-R820 R832 = RES_v2: Res, Chip, 10K, 1/10W, 1%, AEC-Q200, 0402; EN: 101-1-00389; KEY Number: 101-1-00389@2; Mfg: PANASONIC; Mfg Part No: ERJ2RKF1002X; Temperature: -55°C to +155°C
R263 = RES_v2: Res, Chip, 510K, 1/16W, 5%, 0402; EN: 101-1-02834; KEY Number: 101-1-02834@2; Mfg: VISHAY; Mfg Part No: CRCW0402510KJNED; Temperature: -55°C to +155°C
R821 = RES_v2: Res, Chip, 2.2M, 1/16W, 1%, 0402; EN: 101-1-03540; KEY Number: 101-1-03540@1; Mfg: VISHAY; Mfg Part No: CRCW04022M20FKED; Temperature: -55°C to +155°C
SW3 SW8 = SWITCH_PUSH-2_3P_A: Switch, Tactile, SPST-NO, 12V, 50mA, with Boss, RA, SMD; EN: 205-1-00128; KEY Number: 205-1-00128@1; Mfg: OMRON CORP.; Temperature: -25°C to +70°C
U26 = IC_TPS3422_USON-6P_A1: IC, TPS3422, Low-Power, Push-Button Controllers with Configurable Delay, SON-6; EN: 301-0-02216; KEY Number: 301-0-02216@1; Mfg: TEXAS INSTRUMENTS; Mfg Part No: TPS3422EGDRY*; Temperature: -40°C to +125°C
U27 = IC_GATE_BUFX1_5P_H_A1: IC, SN74LV1T126, Single Buffer, 3-State O/P, CMOS Logic Level Shifter, SC70-5; EN: 301-0-02907; KEY Number: 301-0-02907@1; Mfg: TEXAS INSTRUMENTS; Mfg Part No: SN74LV1T126DCKR; Temperature: -40°C to +125°C
X2 = CRYSTAL: XTAL, 32.768KHz, 12.5pF, +/-20ppm, 70K, 3.2x1.5mm, SMD; EN: 108-1-00009; KEY Number: 108-1-00009@1; Mfg: MICRO CRYSTAL; Mfg Part No: CC7V-T1A-32.768KHZ-12.5PF-20PPM-TA-QC; Temperature: -40°C to +85°C
X3 = CRYSTAL_4P: XTAL, 24MHz, 9pF, +/-10ppm, 40E, 2.5x3.2mm, SMD; EN: 108-1-00143; KEY Number: 108-1-00143@1; Mfg: EPSON TOYOCOM; Mfg Part No: TSX-3225 24.0000MF15X-AC5; Temperature: -40°C to +85°C
C105 C109 = CAP_NP: Cap, Cer-X5R, 2.2uF, 10V, 10%, 0402; EN: 102-1-00208; FPLIST: 0402,0402_HD; KEY Number: 102-1-00208@1; Mfg: TDK CORPORATION; Mfg Part No: C1005X5R1A225K; Temperature: -55°C to +85°C
C110 C131 C132 C135 C143 = CAP_NP: Cap, Cer-X5R, 1uF, 16V, 10%, 0402; EN: 102-1-01745; KEY Number: 102-1-01745@3; Mfg: AVX CORPORATION; Mfg Part No: 0402YD105KAT2A; Temperature: -55°C to +85°C
R94-R101 R858 = RES_v2: Res, Chip, 47K, 1/16W, 1%, 0402; EN: 101-1-03402; KEY Number: 101-1-03402@2; Mfg: WALSIN TECHNOLOGY CORP.; Mfg Part No: WR04X4702FTL; Temperature: -55°C to +155°C
R105-R108 R822-R830 = RES_v2: Res, Chip, 22E, 1/10W, 1%, AEC-Q200, 0402; EN: 101-1-03406; KEY Number: 101-1-03406@3; Mfg: PANASONIC; Mfg Part No: ERJ2RKF22R0X; Temperature: -55°C to +155°C
U8 = IC_NAND_FLASHx8_BGA-153P_J_A1: IC, eMMC 5.0, 8GB, x8bit, 52MHz, VFBGA-153; EN: 301-2-00608; KEY Number: 301-2-00608@1; Mfg: MICRON; Mfg Part No: MTFC8GAKAJCN-4M IT; Temperature: -40°C to +85°C
C112 C117 C126 C157 C159 C597 = CAP_NP: Cap, Cer-X5R, 10uF, 10V,  20%, 0402; EN: 102-1-01803; KEY Number: 102-1-01803@6; Mfg: MURATA MANUFACTURING CO,LTD; Mfg Part No: GRM155R61A106ME11D; Temperature: -55°C to +85°C
C114 C166 C168 = CAP_NP: Cap, Cer-X5R, 47uF, 10V, 20%, 0805; EN: 102-1-02136; KEY Number: 102-1-02136@1; Mfg: MURATA MANUFACTURING CO,LTD; Mfg Part No: GRM21BR61A476ME15L; Temperature: -55°C to +85°C
FB1 FB3 FB10-FB20 = FER_BEAD: F-Bead, 120E, 1.3A, SMD0402; EN: 104-1-00007; KEY Number: 104-1-00007@1; Mfg: MURATA MANUFACTURING CO,LTD; Mfg Part No: BLM15PD121SN1B; Temperature: -55°C to +125°C
J2 = CONN_MICROSD-8_12P_B: Conn, uSD card socket, 1x1, Push-Push, RA, SMD; EN: 201-2-00532; KEY Number: 201-2-00532@1; Mfg: WURTH ELECTRONIK, INC; Mfg Part No: 693071010811; Temperature: -25°C to +85°C
P2-P15 = PROT_ZENX2_NET_2P_A: TVS-Zener Diode, Bi, 7V, AEC-Q101, X3DFN-2; EN: 305-1-00135; KEY Number: 305-1-00135@1; Mfg: ON SEMICONDUCTOR; Temperature: -55°C to +150°C
TP3 TP4 = TEST_POINT_SMD: Testpoint, Pad=0.89mm, SM=0.99mm, SMD; EN: 666-1-00039; KEY Number: 666-1-00039@1; Mfg: NA; Mfg Part No: 666-1-00039
U9 = IC_NORFLASH-SPI_8P_EP_G_A1: IC, NOR Flash, 32MB, 133MHz, SPI, 1.7-2V, W-PDFN-8; EN: 301-2-00670; KEY Number: 301-2-00670@1; Mfg: MICRON; Mfg Part No: MT25QU256ABA1EW7-0SIT; Temperature: -40°C to +85°C
C607 = CAP_NP: Cap, Cer-X7R, 0.01uF, 10V, 10%, 0402; EN: 102-1-00001; KEY Number: 102-1-00001@1; Mfg: AVX CORPORATION; Mfg Part No: 0402ZC103KAT2A; Temperature: -55°C to +125°C
D7 D8 = DIODE_LED: LED, Single, Yellow, 0603; EN: 106-4-00385; KEY Number: 106-4-00385@2; Mfg: OSRAM OPTO SEMICONDUCTORS; Mfg Part No: Q65111A3365; Temperature: -30°C to +85°C
J3 = CONN_RJ45-17X2_39P_A_A1: Conn, RJ45 Jack with Magnetics, 2x1, Shielded, 1000BaseT, LED (G, G/Y), RA, TH; EN: 201-2-01595; KEY Number: 201-2-01595@1; Mfg: BEL FUSE INC; Mfg Part No: 0845-2R1T-E4; Temperature: 0°C to +70°C
R109 R116 R120 R124 R131 R134 = RES_v2: Res, Chip, 220E, 1/16W, 5%, AEC-Q200, 0402; EN: 101-1-02753; KEY Number: 101-1-02753@2; Mfg: VISHAY; Mfg Part No: CRCW0402220RJNED; Temperature: -55°C to +155°C
R110 R114 R115 R128 R571 R572 R574 R783-R785 R798 R799 R844-R847 R863 R864 = RES_v2: Res, Chip, 2.2K, 1/10W, 1%, AEC-Q200, 0402; EN: 101-1-03621; KEY Number: 101-1-03621@1; Mfg: KOA SPEER ELECTRONICS, INC.; Mfg Part No: RK73H1ETTP2201F; Temperature: -55°C to +155°C
R112 R117-R119 R122 R123 R125 R126 = RES_v2: Res, Chip, 33E, 1/16W, 1%, 0402; EN: 101-1-03680; KEY Number: 101-1-03680@2; Mfg: WALSIN TECHNOLOGY CORP.; Mfg Part No: WR04X33R0FTL; Temperature: -55°C to +155°C
R113 = RES_v2: Res, Chip, 1.5K, 1/16W, 1%, 0402; EN: 101-1-00310; KEY Number: 101-1-00310@3; Mfg: WALSIN TECHNOLOGY CORP.; Mfg Part No: WR04X1501FTL; Temperature: -55°C to +155°C
R129 = RES_v2: Res, Chip, 4.87K, 1/16W, 1%, 0402; EN: 101-1-04053; KEY Number: 101-1-04053@2; Mfg: WALSIN TECHNOLOGY CORP.; Mfg Part No: WR04X4871FTL; Temperature: -55°C to +155°C
R790-R797 = RES_v2: Res, Chip, 49.9E, 1/16W, 1%, AEC-Q200, 0402; EN: 101-1-04432; KEY Number: 101-1-04432@1; Mfg: VISHAY; Mfg Part No: CRCW040249R9FKED; Temperature: -55°C to +155°C
TP5 TP6 TP48 TP58-TP60 = TEST_POINT_SMD: Testpoint, Pad=1mm, SM=1.3mm, SMD; EN: 666-1-00008; KEY Number: 666-1-00008@1; Mfg: NA; Mfg Part No: 666-1-00008
U10 = IC_DP83849ID_TQFP-80P: IC, DP83849ID, Dual Port, 10/100 Ethernet PHY Transceiver, TQFP-80; EN: 301-5-00050; KEY Number: 301-5-00050@1; Mfg: TEXAS INSTRUMENTS; Mfg Part No: DP83849IDVS/NOPB; Temperature: -40°C to +85°C
U11 U12 U15-U17 = IC_PUSB3F96_DFN-10P: IC, PUSB3F96, ESD Protection, UltraHigh-Speed Interfaces, DFN2510A-10; EN: 301-0-01093; KEY Number: 301-0-01093@1; Mfg: NXP SEMICONDUCTORS; Temperature: -40°C to +85°C
Y1 = OSC_4P_A: Osc, 50MHz, +/-50ppm, 3.3V, HCMOS/TTL, 15pF, SMD; EN: 302-1-00063; KEY Number: 302-1-00063@1; Mfg: ABRACON CORPORATION; Mfg Part No: ASFL1-50.000MHZ-EC-T; Temperature: -20°C to +70°C
C129 C130 = CAP_NP: Cap, Cer-NPO, 33pF, 25V, 1%, 0402; EN: 102-1-00751; KEY Number: 102-1-00751@1; Mfg: AVX CORPORATION; Mfg Part No: 04023A330FAT2A; Temperature: -55°C to +125°C
C589 = CAP_NP: Cap, Cer-X5R, 4.7uF, 16V, 10%, 0603; EN: 102-1-00091; KEY Number: 102-1-00091@4; Mfg: MURATA MANUFACTURING CO,LTD; Mfg Part No: GRM188R61C475KAAJD; Temperature: -55°C to +85°C
L7 = IND_CORE_B: Ind, Power, 4.7uH, 20%, 0.8A, 225mE, Shielded, 25MHz, SMD1008; EN: 103-1-00452; KEY Number: 103-1-00452@1; Mfg: MURATA MANUFACTURING CO,LTD; Mfg Part No: LQM2HPN4R7MGC*; Temperature: -55°C to +125°C
R148 = RES_v2: Res, Chip, 1M, 1/10W, 1%, AEC-Q200, 0402; EN: 101-1-00581; KEY Number: 101-1-00581@1; Mfg: KOA SPEER ELECTRONICS, INC.; Mfg Part No: RK73H1ETTP1004F; Temperature: -55°C to +155°C
R577 = RES_v2: Res, Chip, 12K, 1/16W, 1%, 0402; EN: 101-1-03373; KEY Number: 101-1-03373@1; Mfg: YAGEO; Mfg Part No: RC0402FR-0712KL; Temperature: -55°C to +155°C
U13 = IC_EEPROM-I2C_8P_EP_B_A1: IC, EEPROM, 256B, 1MHz, I2C, UDFN-8; EN: 301-2-00235; KEY Number: 301-2-00235@1; Mfg: ATMEL; Mfg Part No: AT24C02C-MAHM-*; Temperature: -40°C to +85°C
U14 = IC_USB2517_QFN-64P_EP_CUST_A1: IC, USB2517I, USB HUB, 7-Ports, QFN-64; EN: 301-0-02320; KEY Number: 301-0-02320@1; Mfg: MICROCHIP; Mfg Part No: USB2517I-JZX; Temperature: -40°C to +85°C
X1 = CRYSTAL_4P_D: XTAL, 24MHz, 18pF, +/-30ppm, 60E, 2.5x3.2mm, SMD; EN: 108-1-00004; KEY Number: 108-1-00004@1; Mfg: CTS Corporation; Mfg Part No: 403C35D24M00000
C149 C151 C153 C155 = CAP_NP: Cap, Cer-X5R, 22uF, 10V, 20%, 0603; EN: 102-1-01791; KEY Number: 102-1-01791@2; Mfg: WALSIN TECHNOLOGY CORP.; Mfg Part No: 0603X226M100CT; Temperature: -55°C to +85°C
DA1-DA5 = DIODE_NETX2_LED-GR_4P: LED, Single, (Green/Red), SMD0603; EN: 106-4-00053; KEY Number: 106-4-00053@1; Mfg: AVAGO TECHNOLOGIES; Temperature: -40°C to +85°C
R150 R151 R153 R157 R158 = RES_v2: Res, Chip, 470E, 1/16W, 1%, 100ppm/degC, 0402; EN: 101-1-03571; FPLIST: 0402,0402_HD; KEY Number: 101-1-03571@1; Mfg: VISHAY; Mfg Part No: CRCW0402470RFK; Temperature: -55°C to +155°C
U18 = IC_PWRSWITCHx4_16P_C_A1: IC, TPS2054B, Current-Limited Power-Distribution Switches, SOIC-16; EN: 301-0-00042; KEY Number: 301-0-00042@1; Mfg: TEXAS INSTRUMENTS
U19 = IC_PWRSWITCH_8P_D_A1: IC, MIC2026, Dual Channel Power Distribution Switch, SOIC-8; EN: 301-0-01642; KEY Number: 301-0-01642@1; Mfg: MICROCHIP; Temperature: -40°C to +85°C
FL1-FL6 = FIL_COM-MODE_4P_C_POL: Filter, Choke coil, CM, 90E, 330mA, Signal Line, SMD; EN: 303-0-00024; KEY Number: 303-0-00024@1; Mfg: MURATA MANUFACTURING CO,LTD; Temperature: -40°C to +85°C
J4 J5 = CONN_USBA-4X2_12P: Conn, USB Type-A Receptacle, 2x1, Shielded, Stacked, RA, TH; EN: 201-2-01591; KEY Number: 201-2-01591@1; Mfg: TE CONNECTIVITY; Mfg Part No: 5787617-1; Temperature: -55°C to +85°C
J6 = CONN_USBA-4X1_8P: Conn, USB 2.0, Type-A, Receptacle, 1x1, Shielded, RA, TH; EN: 201-2-01378; KEY Number: 201-2-01378@1; Mfg: TE CONNECTIVITY; Mfg Part No: 1-1734775-1; Temperature: 0°C to +50°C
J7 = CONN_USB-5X1_9P: Conn, USB 2.0 Micro AB Receptacle, 1x1, Shielded, RA, SMD; EN: 201-2-00027; KEY Number: 201-2-00027@1; Mfg: FCI - AMPHENOL ICC; Mfg Part No: 10104111-0001LF; Temperature: -30°C to +80°C

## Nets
GND: C102.2 C103.2 C104.2 C105.2 C106.2 C107.2 C108.2 C109.2 C110.2 C111.2 C112.2 C113.2 C114.2 C115.2 C116.2 C117.2 C118.2 C119.2 C120.2 C121.2 C122.1 C123.1 C124.1 C125.1 C126.2 C127.2 C128.2 C129.2 C130.2 C131.2 C132.2 C133.2 C134.2 C135.2 C136.2 C137.2 C138.2 C139.2 C140.2 C141.2 C142.2 C143.2 C149.2 C150.2 C151.2 C152.2 C153.2 C154.2 C155.2 C156.2 C157.2 C158.2 C159.2 C160.2 C161.2 C162.2 C163.2 C164.2 C165.2 C166.2 C167.1 C168.2 C169.1 C200.2 C201.2 C204.2 C205.2 C573.2 C574.2 C575.2 C576.2 C577.2 C589.2 C591.1 C592.1 C593.1 C594.1 C597.2 C598.2 C599.2 C601.1 C602.1 C603.1 C604.1 C605.1 C606.1 C607.2 DA1.4(RK) DA2.4(RK) DA3.4(RK) DA4.4(RK) DA5.4(RK) FB15.1 FB16.1 J2.6(VSS) J3.S1 J3.S2 J3.S3 J3.S4 J4.4(GND1) J4.8(GND2) J4.S1 J4.S2 J4.S3 J4.S4 J5.4(GND1) J5.8(GND2) J5.S1 J5.S2 J5.S3 J5.S4 J6.4(GND) J6.S1 J6.S2 J6.S3 J6.S4 J7.S1 J7.S2 J7.S3 J7.S4 P2.1 P3.1 P4.1 P5.1 P6.1 P7.1 P8.1 P9.1 P10.1 P11.1 P12.1 P13.1 P14.1 P15.1 R103.1 R121.1 R127.1 R129.2 R133.2 R135.1 R144.2 R145.2 R146.2 R147.2 R149.2 R152.2 R154.2 R166.2 R572.2 R574.2 R577.1 R579.2 R772.2 R821.1 R832.1 R836.2 SW3.1 SW3.3 SW8.1 SW8.3 U6.N7(TEST_MODE) U8.A6(VSS1) U8.C4(VSSQ1) U8.E7(VSS2) U8.G5(VSS3) U8.H10(VSS4) U8.J5(VSS5) U8.K8(VSS6) U8.N2(VSSQ2) U8.N5(VSSQ3) U8.P4(VSSQ4) U8.P6(VSSQ5) U9.4(VSS) U9.9(VSS_EP) U10.6(COREGND1) U10.10(IOGND1) U10.22(ANAGND1) U10.25(CDGND1) U10.29(ANAGND2) U10.33(ANAGND3) U10.37(CDGND2) U10.40(ANAGND4) U10.52(IOGND2) U10.55(COREGND2) U10.64(IOGND3) U10.77(IOGND4) U11.3(GND1) U11.8(GND2) U12.3(GND1) U12.8(GND2) U13.1(A0) U13.2(A1) U13.3(A2) U13.4(GND) U13.7(WP) U13.9(GND_EP) U14.19(TEST) U14.65(VSS_EP) U15.3(GND1) U15.8(GND2) U16.3(GND1) U16.8(GND2) U17.3(GND1) U17.8(GND2) U18.1(GND1) U18.5(GND2) U19.6(GND) U26.2(GND) U26.6(TST) U27.3(GND) X1.2 X1.4 X3.2(GND1) X3.4(GND2) Y1.2(GND) ; also on sheet 3 4 5 6 7 8 9 17 18 19 20 21
VBUS1_FL: C601.2 FB10.2 J4.1(VBUS1) P9.2
VBUS2_FL: C602.2 FB11.2 J4.5(VBUS2) P10.2
VBUS3_FL: C603.2 FB12.2 J5.1(VBUS1) P11.2
VBUS4_FL: C604.2 FB13.2 J5.5(VBUS2) P12.2
VBUS5_FL: C605.2 FB14.2 J6.1(VBUS) P13.2
VBUS_DET_HUB: R140.2 U14.44(VBUS_DET)
VCCI_eMMC: C110.1 C111.1 U8.C2(VDDIM)
VDD_1V8: C106.1 C107.1 C108.1 C109.1 C112.1 C113.1 R94.1 R95.1 R96.1 R97.1 R98.1 R99.1 R100.1 R101.1 R102.1 R104.2 R858.1 U8.C6(VCCQ1) U8.M4(VCCQ2) U8.N4(VCCQ3) U8.P3(VCCQ4) U8.P5(VCCQ5) U9.8(VCC) ; also on sheet 5 8 18 19 20
VDD_CENT_TAP_A1: C122.2 FB17.2 J3.7(TRCT1[1])
VDD_CENT_TAP_A2: C123.2 FB18.2 J3.12(TRCT2[1])
VDD_CENT_TAP_B1: C124.2 FB19.2 J3.14(TRCT1[2])
VDD_CENT_TAP_B2: C125.2 FB20.2 J3.22(TRCT2[2])
VDD_ETH_ANA_3V3: C116.1 FB1.2 U10.30(ANA33VDD)
VDD_EXT_LS_5V0: C157.1 C158.1 C165.1 U18.2(IN1) U19.7(IN) ; also on sheet 5 18
VDD_HUB_LED: D9.1(K) DA1.1(GA) DA2.1(GA) DA3.1(GA) DA4.1(GA) DA5.1(GA)
VDD_NVCC_3V3: C102.1 C573.1 R137.1 R138.1 R164.1 R181.1 R182.1 R578.1 R580.1 R581.1 R839.1 R840.1 R866.1 R867.1 R868.1 R869.1 R870.1 R871.1 R874.1 U6.H13(NVCC_UART) U26.4(VCC) U27.5(VCC) ; also on sheet 4 8 9 20
VDD_OTG1_VBUS: C168.1 C169.2 FB3.1 U19.5(OUTB)
VDD_PERI_3V3: C103.1 C104.1 C105.1 C114.1 C115.1 C117.1 C118.1 C119.1 C120.1 C121.1 C128.1 C597.1 C607.1 D9.2(A) FB1.1 FB17.1 FB18.1 FB19.1 FB20.1 J2.4(VDD) L7.1 R77.1 R109.1 R110.2 R113.2 R114.2 R115.2 R116.1 R120.2 R124.1 R128.2 R130.2 R131.1 R134.1 R571.1 R783.2 R784.2 R785.2 R798.2 R799.2 R810.2 R811.2 R812.2 R813.2 R844.1 R845.2 R846.1 R847.2 R863.1 R864.1 U8.E6(VCC1) U8.F5(VCC2) U8.J10(VCC3) U8.K9(VCC4) U10.11(IOVDD1) U10.51(IOVDD2) U10.65(IOVDD3) U10.78(IOVDD4) U13.8(VCC) Y1.4(VDD) ; also on sheet 5 17 18 19 20
VDD_PERI_FIL_3V3: C131.1 C133.1 C137.1 C138.1 C139.1 C140.1 C141.1 C142.1 C143.1 C589.1 L7.2 R140.1 R141.1 R142.1 R143.1 R161.1 R162.1 R163.1 R165.1 R816.2 R817.2 R818.2 R819.2 R820.2 U14.5(VDDA33) U14.10(VDDA33) U14.24(VDD33CR) U14.46(VDD33) U14.52(VDDA33) U14.57(VDDA33) U14.64(VDD33PLL)
VDD_PMIC_LS_5V0: C159.1 C160.1 U18.6(IN2) ; also on sheet 5 9 18
VDD_SNVS_IN: R27.1 ; also on sheet 4 5 6 20
VDD_USB_VBUS1: C149.1 C150.1 FB10.1 U18.15(OUT1)
VDD_USB_VBUS2: C151.1 C152.1 FB11.1 U18.14(OUT2)
VDD_USB_VBUS3: C153.1 C154.1 FB12.1 U18.11(OUT3)
VDD_USB_VBUS4: C155.1 C156.1 FB13.1 U18.10(OUT4)
VDD_USB_VBUS5: C166.1 C167.2 FB14.1 U19.8(OUTA)
BOOST0: R149.1 U14.50(LEDB1#/BOOST0)
BOOST1: R152.1 U14.48(LEDB2#/BOOST1)
BOOT_MODE0: U6.T10(BOOT_MODE0) ; also on sheet 20
BOOT_MODE1: U6.U10(BOOT_MODE1) ; also on sheet 20
CCM_PMIC_STBY_REQ: R765.1 U6.U9(CCM_PMIC_STBY_REQ)
CLOCK_50MHZ: R132.1 Y1.3(OUT)
CMD: R830.2 U8.M5(CMD)
CRS_DV_A: R119.2 R572.1 U10.1(CRS_A/CRS_DV_A/LED_CFG_A)
CRS_DV_B: R126.2 R574.1 U10.61(CRS_B/CRS_DV_B/LED_CFG_B)
DAT0: R822.2 U8.A3(DAT0)
DAT1: R823.2 U8.A4(DAT1)
DAT2: R824.2 U8.A5(DAT2)
DAT3: R825.2 U8.B2(DAT3)
DAT4: R826.2 U8.B3(DAT4)
DAT5: R827.2 U8.B4(DAT5)
DAT6: R828.2 U8.B5(DAT6)
DAT7: R829.2 U8.B6(DAT7)
ED_EN_A: R798.1 U10.9(RXD3_A/ED_EN_A)
ED_EN_B: R799.1 U10.53(RXD3_B/ED_EN_B)
EEPR_SCL: R136.2 U13.6(SCL)
EEPR_SDA: R139.2 U13.5(SDA)
ENET_INT_A: R861.1 R863.2 U10.18(PWRDOWN#_INT_A)
ENET_INT_B: R862.1 R864.2 U10.44(PWRDOWN#_INT_B)
ENET_REF_CLK: U10.68(CLK2MAC) ; also on sheet 8
ENETPHY_RESET#: R127.2 TP48.1 U10.71(RESET#) ; also on sheet 9
EXT_EN: R571.2 U10.56(RXD2_B)
GANG_EN: R154.1 U14.34(LEDB3#/GANG_EN)
GPANIO: U6.R13(GPANIO)
GPIO1_IO22: R841.1 ; also on sheet 20
GPIO1_IO24: R861.2 U6.H17(UART3_TX_DATA)
GPIO1_IO25: R862.2 U6.H16(UART3_RX_DATA)
GPIO5_IO02: R834.2 ; also on sheet 20
GPIO5_IO03: R835.2 ; also on sheet 20
GPIO5_IO04: R866.2 U6.P9(SNVS_TAMPER4) ; also on sheet 20
GPIO5_IO05: R867.2 U6.N8(SNVS_TAMPER5) ; also on sheet 20
GPIO5_IO06: R868.2 U6.N11(SNVS_TAMPER6) ; also on sheet 20
GPIO5_IO07: R869.2 U6.N10(SNVS_TAMPER7) ; also on sheet 20
GPIO5_IO08: R870.2 U6.N9(SNVS_TAMPER8) ; also on sheet 20
GPIO5_IO09: R871.2 U6.R6(SNVS_TAMPER9) ; also on sheet 20
HUB_CFG_SEL1: R142.2 R146.1 U14.42(HS_IND/CFG_SEL1)
HUB_CFG_SEL2: R143.2 R147.1 U14.13(CFG_SEL2)
HUB_LEDA1#: DA1.2(RA) DA1.3(GK) R150.2
HUB_LEDA2#: DA2.2(RA) DA2.3(GK) R151.2
HUB_LEDA3#: DA3.2(RA) DA3.3(GK) R153.2
HUB_LEDA4#: DA4.2(RA) DA4.3(GK) R157.2
HUB_LEDA5#: DA5.2(RA) DA5.3(GK) R158.2
HUB_OCS1#: C161.1 R155.2 U14.28(OCS1#)
HUB_OCS2#: C162.1 R156.2 U14.27(OCS2#)
HUB_OCS3#: C163.1 R159.2 U14.22(OCS3#)
HUB_OCS4#: C164.1 R160.2 U14.21(OCS4#)
HUB_OCS5#: R820.1 U14.35(OCS5#) U19.2(FLGA#)
HUB_PWR_EN1: U14.29(PRTPWR1) U18.3(EN1)
HUB_PWR_EN2: U14.26(PRTPWR2) U18.4(EN2)
HUB_PWR_EN3: U14.23(PRTPWR3) U18.7(EN3)
HUB_PWR_EN4: U14.20(PRTPWR4) U18.8(EN4)
HUB_PWR_EN5: U14.30(PRTPWR5) U19.1(ENA)
HUB_RESET#: R144.1 TP60.1 U14.43(RESET#) ; also on sheet 9
HUB_VDDA18PLL: C132.1 C134.1 U14.62(VDD18PLL)
HUB_VDDDIG18: C135.1 C136.1 U14.25(VDD18)
I2C2_CURSENSE_SCL: R181.2 U6.F17(UART5_TX_DATA) ; also on sheet 18
I2C2_CURSENSE_SDA: R182.2 U6.G13(UART5_RX_DATA) ; also on sheet 18
I2C4_HUB_EEPR_SCL: R89.1 R136.1 R137.2 R145.1 TP59.1 U14.41(SCL/SMBCLK/CFG_SEL0)
I2C4_HUB_EEPR_SDA: R90.1 R138.2 R139.1 TP58.1 U14.40(SDA/SMBDATA/NON_REM1)
I2C4_SCL: R89.2 U6.J17(UART2_TX_DATA)
I2C4_SDATA: R90.2 U6.J16(UART2_RX_DATA)
i.MX_ONOFF: C598.1 SW3.2 U6.R8(ONOFF)
JTAG_MOD: U6.P15(JTAG_MOD) ; also on sheet 17
JTAG_TCK: U6.M14(JTAG_TCK) ; also on sheet 17
JTAG_TDI: U6.N16(JTAG_TDI) ; also on sheet 17
JTAG_TDO: U6.N15(JTAG_TDO) ; also on sheet 17
JTAG_TMS: U6.P14(JTAG_TMS) ; also on sheet 17
JTAG_TRST#: U6.N14(JTAG_TRST#) ; also on sheet 17
LCD_PWR_EN: U6.H14(UART2_RTS#) ; also on sheet 19
LED_ACT/COL_A: D7.1(K) R110.1 U10.21(LED_ACT/LED_COL/AN_EN_A)
LED_ACT/COL_B: D8.1(K) R128.1 U10.41(LED_ACT/LED_COL/AN_EN_B)
LED_LINK_A: J3.31(GK2) R844.2 U10.19(LED_LINK_A/AN0_A)
LED_LINK_B: J3.27(GK1) R846.2 U10.43(LED_LINK_B/AN0_B)
LED_SPEED_A: J3.34(GA/YK[2]) R845.1 U10.20(LED_SPEED_A/FXSD_A/AN1_A)
LED_SPEED_B: J3.30(GA/YK[1]) R847.1 U10.42(LED_SPEED_B/FXSD_B/AN1_B)
LOCAL_PWR: R141.2 U14.45(SUSP_IND/LOCAL_PWR/NON_REM0)
MII_MODE_A: R783.1 U10.80(RX_DV_A/MII_MODE_A)
MII_MODE_B: R784.1 U10.62(RX_DV_B/MII_MODE_B)
OTG_DM: FL6.2 J7.2(D-) U17.1(CH1) U17.10(NC4)
OTG_DP: FL6.3 J7.3(D+) U17.2(CH2) U17.9(NC3)
OTG_PWR: C606.2 FB3.2 J7.1(VBUS) U17.5(CH4) U17.6(NC1)
PB_RESET: D27.1(K) SW8.2
PFBIN: C126.1 C127.1 C574.1 C575.1 C576.1 C577.1 U10.7(PFBIN1) U10.28(PFBIN2) U10.31(PFBOUT) U10.34(PFBIN3) U10.54(PFBIN4)
PFO#: R27.2 R860.1 U6.R9(SNVS_TAMPER1)
PHY_MDC: TP5.1 U10.67(MDC) ; also on sheet 9
PHY_MDIO: R113.1 TP6.1 U10.66(MDIO) ; also on sheet 9
PHYA_CRSDV: R119.1 ; also on sheet 8
PHYA_MDI_1_N: J3.13(TRD1-[1]) R791.2 U10.26(TPTDM_A/FXTDM_A) U11.2(CH2) U11.9(NC3)
PHYA_MDI_1_P: J3.6(TRD1+[1]) R790.1 U10.27(TPTDP_A/FXTDP_A) U11.1(CH1) U11.10(NC4)
PHYA_MDI_2_N: J3.5(TRD2-[1]) R793.2 U10.23(TPRDM_A/FXRDM_A) U11.5(CH4) U11.6(NC1)
PHYA_MDI_2_P: J3.11(TRD2+[1]) R792.1 U10.24(TPRDP_A/FXRDP_A) U11.4(CH3) U11.7(NC2)
PHYA_RXD0: R112.2 ; also on sheet 8
PHYA_RXD1: R117.2 ; also on sheet 8
PHYA_RXER: R114.1 R118.2 ; also on sheet 8
PHYA_TX_EN: U10.13(TX_EN_A) ; also on sheet 8
PHYA_TXD0: U10.14(TXD0_A) ; also on sheet 8
PHYA_TXD1: U10.15(TXD1_A) ; also on sheet 8
PHYB_CRSDV: R126.1 ; also on sheet 8
PHYB_MDI_1_N: J3.21(TRD1-[2]) R795.2 U10.36(TPTDM_B/FXTDM_B) U12.2(CH2) U12.9(NC3)
PHYB_MDI_1_P: J3.15(TRD1+[2]) R794.1 U10.35(TPTDP_B/FXTDP_B) U12.1(CH1) U12.10(NC4)
PHYB_MDI_2_N: J3.16(TRD2-[2]) R797.2 U10.39(TPRDM_B/FXRDM_B) U12.5(CH4) U12.6(NC1)
PHYB_MDI_2_P: J3.23(TRD2+[2]) R796.1 U10.38(TPRDP_B/FXRDP_B) U12.4(CH3) U12.7(NC2)
PHYB_RXD0: R122.2 ; also on sheet 8
PHYB_RXD1: R123.2 ; also on sheet 8
PHYB_RXER: R115.1 R125.2 ; also on sheet 8
PHYB_TX_EN: U10.49(TX_EN_B) ; also on sheet 8
PHYB_TXD0: U10.48(TXD0_B) ; also on sheet 8
PHYB_TXD1: U10.47(TXD1_B) ; also on sheet 8
PMIC_I2C1_SCL: R580.2 U6.G17(UART4_TX_DATA) ; also on sheet 4 17
PMIC_I2C1_SDA: R581.2 U6.G16(UART4_RX_DATA) ; also on sheet 4 17
PMIC_PB: R841.2 U6.J15(UART2_CTS#) ; also on sheet 4
PMIC_PFO#: R860.2 ; also on sheet 4
PMIC_PWR_EN: R88.2 R833.1 U26.1(RST#) ; also on sheet 4
PMIC_PWR_EN_R: R88.1 U6.T9(SNVS_PMIC_ON_REQ)
PMIC_STBY_REQ: R765.2 ; also on sheet 4
PMIC_WAKE#: U6.R10(SNVS_TAMPER0) ; also on sheet 4
POR_B: U6.P8(POR#) U27.1(OE) ; also on sheet 4 17
PRTDIS_M6: R162.2 U14.53(USBDN6_DM/PRT_DIS_M6)
PRTDIS_M7: R165.2 U14.55(USBDN7_DM/PRT_DIS_M7)
PRTDIS_P6: R161.2 U14.54(USBDN6_DP/PRT_DIS_P6)
PRTDIS_P7: R163.2 U14.56(USBDN7_DP/PRT_DIS_P7)
QSPIA_DATA0: TP3.1 U9.5(DQ0) ; also on sheet 8
QSPIA_DATA1: U9.2(DQ1) ; also on sheet 8
QSPIA_DATA2: U9.3(W#/DQ2) ; also on sheet 8
QSPIA_DATA3: U9.7(HOLD#/DQ3) ; also on sheet 8
QSPIA_SCLK: TP4.1 U9.6(C) ; also on sheet 8
QSPIA_SS0#: R104.1 U9.1(S#) ; also on sheet 8
RBIAS: R129.1 U10.32(RBIAS)
RBIAS_HUB: R577.2 U14.63(RBIAS)
REVRES_1: R834.1 R836.1 R839.2 U6.P11(SNVS_TAMPER2)
REVRES_2: R772.1 R835.1 R840.2 U6.P10(SNVS_TAMPER3)
RTC_XTALI: C200.1 U6.T11(RTC_XTALI) X2.1
RTC_XTALO: C201.1 U6.U11(RTC_XTALO) X2.2
RXD0_A: R112.1 R785.1 U10.4(RXD0_A/PHYAD1)
RXD0_B: R122.1 U10.58(RXD0_B/PHYAD3)
RXD1_A: R117.1 U10.5(RXD1_A/PHYAD2)
RXD1_B: R123.1 U10.57(RXD1_B/PHYAD4)
RXER_A: R118.1 U10.2(RX_ER_A/MDIX_EN_A)
RXER_B: R125.1 U10.60(RX_ER_B/MDIX_EN_B)
SD1_CD#: J2.CD1 J2.CD2 P2.2 R77.2 R87.1
SD1_CD#_R: R87.2 U6.J14(UART1_RTS#)
SD1_CLK: J2.5(CLK) P5.2 ; also on sheet 8
SD1_CMD: J2.3(CMD) P6.2 ; also on sheet 8
SD1_DATA0: R107.1 ; also on sheet 8
SD1_DATA1: R108.1 ; also on sheet 8
SD1_DATA2: R105.1 ; also on sheet 8
SD1_DATA3: R106.1 ; also on sheet 8
SD2_CLK: U8.M6(CLK) ; also on sheet 8
SD2_CMD: R102.2 R830.1 ; also on sheet 8
SD2_DATA0: R94.2 R822.1 ; also on sheet 8
SD2_DATA1: R95.2 R823.1 ; also on sheet 8
SD2_DATA2: R96.2 R824.1 ; also on sheet 8
SD2_DATA3: R97.2 R825.1 ; also on sheet 8
SD2_DATA4: R98.2 R826.1 ; also on sheet 8
SD2_DATA5: R99.2 R827.1 ; also on sheet 8
SD2_DATA6: R100.2 R828.1 ; also on sheet 8
SD2_DATA7: R829.1 R858.2 ; also on sheet 8
SD2_RESET#: R101.2 U8.K5(RST#) ; also on sheet 8
SD2_STROBE: R103.2 U8.H5(DS)
SDCARD_DAT0: J2.7(DAT0) P4.2 R107.2
SDCARD_DAT1: J2.8(DAT1) P3.2 R108.2
SDCARD_DAT2: J2.1(DAT2) P8.2 R105.2
SDCARD_DAT3: J2.2(CD/DAT3) P7.2 R106.2
ST_HUB_LEDA1#: R150.1 U14.51(LEDA1#/PRT_SWP1)
ST_HUB_LEDA2#: R151.1 U14.49(LEDA2#/PRT_SWP2)
ST_HUB_LEDA3#: R153.1 U14.47(LEDA3#/PRT_SWP3)
ST_HUB_LEDA4#: R157.1 U14.33(LEDA4#/PRT_SWP4)
ST_HUB_LEDA5#: R158.1 U14.31(LEDA5#/PRT_SWP5)
SYS_nRST: C599.1 D27.2(A) D28.2(A) R833.2 R874.2 U26.3(PB1)
TOUCH_BUSY: U6.G14(UART3_RTS#) ; also on sheet 19
TOUCH_INTR_REQ#: U6.H15(UART3_CTS#) ; also on sheet 19
TPS2054_OC1#: R155.1 R816.1 U18.16(OC1#)
TPS2054_OC2#: R156.1 R817.1 U18.13(OC2#)
TPS2054_OC3#: R159.1 R818.1 U18.12(OC3#)
TPS2054_OC4#: R160.1 R819.1 U18.9(OC4#)
UART1_CTS#: R832.2 U6.K15(UART1_CTS#)
UART1_RX_DATA: U6.K16(UART1_RX_DATA) ; also on sheet 17
UART1_TX_DATA: U6.K14(UART1_TX_DATA) ; also on sheet 17
USB_HOST_DN: U14.58(USBUP_DM) ; also on sheet 9
USB_HOST_DP: U14.59(USBUP_DP) ; also on sheet 9
USB_OTG1_DN: FL6.1 ; also on sheet 9
USB_OTG1_DP: FL6.4 ; also on sheet 9
USB_OTG1_FAULT#: U19.3(FLGB#) ; also on sheet 9
USB_OTG1_ID: J7.4(ID) U17.4(CH3) U17.7(NC2) ; also on sheet 9
USB_OTG1_PWREN: R164.2 R166.1 U19.4(ENB) ; also on sheet 9
USBDM_FL1: FL1.2 J4.2(D1-) U15.5(CH4) U15.6(NC1)
USBDM_FL2: FL2.2 J4.6(D2-) U15.2(CH2) U15.9(NC3)
USBDM_FL3: FL3.2 J5.2(D1-) U16.5(CH4) U16.6(NC1)
USBDM_FL4: FL4.2 J5.6(D2-) U16.2(CH2) U16.9(NC3)
USBDM_FL5: FL5.2 J6.2(D-) P15.2
USBDN1_DM: FL1.1 U14.1(USBDN1_DM/PRT_DIS_M1)
USBDN1_DP: FL1.4 U14.2(USBDN1_DP/PRT_DIS_P1)
USBDN2_DM: FL2.1 U14.3(USBDN2_DM/PRT_DIS_M2)
USBDN2_DP: FL2.4 U14.4(USBDN2_DP/PRT_DIS_P2)
USBDN3_DM: FL3.1 U14.6(USBDN3_DM/PRT_DIS_M3)
USBDN3_DP: FL3.4 U14.7(USBDN3_DP/PRT_DIS_P3)
USBDN4_DM: FL4.1 U14.8(USBDN4_DM/PRT_DIS_M4)
USBDN4_DP: FL4.4 U14.9(USBDN4_DP/PRT_DIS_P4)
USBDN5_DM: FL5.1 U14.11(USBDN5_DM/PRT_DIS_M5)
USBDN5_DP: FL5.4 U14.12(USBDN5_DP/PRT_DIS_P5)
USBDP_FL1: FL1.3 J4.3(D1+) U15.4(CH3) U15.7(NC2)
USBDP_FL2: FL2.3 J4.7(D2+) U15.1(CH1) U15.10(NC4)
USBDP_FL3: FL3.3 J5.3(D1+) U16.4(CH3) U16.7(NC2)
USBDP_FL4: FL4.3 J5.7(D2+) U16.1(CH1) U16.10(NC4)
USBDP_FL5: FL5.3 J6.3(D+) P14.2
WDOG_ANY: R771.2 U27.2(A) ; also on sheet 9
X1_ENETPHY: R132.2 U10.70(X1)
XTALI: C204.1 R263.2 R821.2 U6.T16(XTALI) X3.3
XTALIN_HUB: C129.1 R148.1 U14.61(XTAL1/CLKIN) X1.1
XTALO: C205.1 R263.1 U6.T17(XTALO) X3.1
XTALOUT_HUB: C130.1 R148.2 U14.60(XTAL2) X1.3
N20264538: FB16.2 J2.COM1(COMMON1) J2.COM2(COMMON2)
N20323615: R130.1 R133.1 Y1.1(EN)
N20326291: J3.32(GA2) R116.2
N20327026: D7.2(A) R109.2
N20327568: J3.28(GA1) R131.2
N20327935: D8.2(A) R124.2
N20368037: FB15.2 J7.5(GND)
N20429331: D28.1(K) R771.1 U27.4(Y)
N20436944: J3.1(GND1) J3.2(TRD4-[1]) J3.3(TRD3+[1]) J3.4(TRCT3[1]) J3.8(TRD4+[1]) J3.9(TRCT4[1]) J3.10(TRD3-[1]) R121.2
N20467513: R578.2 R579.1 U26.5(TS)
N20496187: J3.17(TRCT3[2]) J3.18(TRD3+[2]) J3.19(TRD4-[2]) J3.20(GND2) J3.24(TRD3-[2]) J3.25(TRCT4[2]) J3.26(TRD4+[2]) R135.2
N20681531: C591.2 R790.2 R791.1 R810.1
N20684634: C592.2 R792.2 R793.1 R811.1
N20685468: C593.2 R794.2 R795.1 R812.1
N20685796: C594.2 R796.2 R797.1 R813.1
N20866761: J3.33(GK/YA[2]) R120.1
N20868982: J3.29(GK/YA[1]) R134.2

Not connected (* = marked no-connect by the designer): U6 P16(CCM_CLK1_N)* P17(CCM_CLK1_P)*; U8 A1(NC1)* A2(NC2)* A7(RFU1)* A8(NC3)* A9(NC4)* A10(NC5)* A11(NC6)* A12(NC7)* A13(NC8)* A14(NC9)* B1(NC10)* B7(NC11)* B8(NC12)* B9(NC13)* B10(NC14)* B11(NC15)* B12(NC16)* B13(NC17)* B14(NC18)* C1(NC19)* C3(NC20)* C5(NC21)* C7(NC22)* C8(NC23)* C9(NC24)* C10(NC25)* C11(NC26)* C12(NC27)* C13(NC28)* C14(NC29)* D1(NC30)* D2(NC31)* D3(NC32)* D4(NC33)* D12(NC34)* D13(NC35)* D14(NC36)* E1(NC37)* E2(NC38)* E3(NC39)* E5(RFU2)* E8(RFU3)* E9(RFU4)* E10(RFU5)* E12(NC40)* E13(NC41)* E14(NC42)* F1(NC43)* F2(NC44)* F3(NC45)* F10(RFU6)* F12(NC46)* F13(NC47)* F14(NC48)* G1(NC49)* G2(NC50)* G3(NC51)* G10(RFU7)* G12(NC52)* G13(NC53)* G14(NC54)* H1(NC55)* H2(NC56)* H3(NC57)* H12(NC58)* H13(NC59)* H14(NC60)* J1(NC61)* J2(NC62)* J3(NC63)* J12(NC64)* J13(NC65)* J14(NC66)* K1(NC67)* K2(NC68)* K3(NC69)* K6(RFU8)* K7(RFU9)* K10(RFU10)* K12(NC70)* K13(NC71)* K14(NC72)* L1(NC73)* L2(NC74)* L3(NC75)* L12(NC76)* L13(NC77)* L14(NC78)* M1(NC79)* M2(NC80)* M3(NC81)* M7(NC82)* M8(NC83)* M9(NC84)* M10(NC85)* M11(NC86)* M12(NC87)* M13(NC88)* M14(NC89)* N1(NC90)* N3(NC91)* N6(NC92)* N7(NC93)* N8(NC94)* N9(NC95)* N10(NC96)* N11(NC97)* N12(NC98)* N13(NC99)* N14(NC100)* P1(NC101)* P2(NC102)* P7(NC103)* P8(NC104)* P9(NC105)* P10(RFU11)* P11(NC106)* P12(NC107)* P13(NC108)* P14(NC109)*; U10 3(COL_A/FX_EN_A)* 8(RXD2_A/CLK2MAC_DIS)* 12(TX_CLK_A)* 16(TXD2_A)* 17(TXD3_A/SNI_MODE_A)* 45(TXD3_B/SNI_MODE_B)* 46(TXD2_B)* 50(TX_CLK_B)* 59(COL_B/FX_EN_B)* 63(RX_CLK_B)* 69(X2)* 72(TCK)* 73(TDO)* 74(TMS)* 75(TRST#)* 76(TDI)* 79(RX_CLK_A)*; U14 14(LEDB7#)* 15(LEDA7#/PRT_SWP7)* 16(LEDB6#)* 17(LEDA6#/PRT_SWP6)* 18(LEDB5#)* 32(LEDB4#)* 36(PRTPWR7)* 37(OCS7#)* 38(OCS6#)* 39(PRTPWR6)*

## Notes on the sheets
sheet 10
- i.MX CONTROL
- NM
- NM
- PU (100K)
- PU (100K)
- NM
- NM
- Mount 2.2M res
  close to XTALI
  pin
- PD(100K)
- PU (100K)
- NM
- NM
- ONOFF BUTTON
- RESET LOGIC
- NM
- NM
- NM
- NM
- NM
- NM
sheet 11
- eMMC
- Layout note: Decoupling capacitor
  should connect close to power and
  ground
- Pull up Resistors on  SD2_DATA,
  SD2_CMD lines are for avoiding bus
  floating
- U15 intended to use in HS200
  mode. For that VCCQ need to
  maintain as 1V8
sheet 12
- NOR FLASH
- uSD CARD
- NM
sheet 13
- ETHERNET PHY
- NM
- NM
- NM
- NM
- NM
- NM
- NM
- Place each 0.1uF
  near to each PFBIN
  pins
- NM
- PHYA ADDR=0b00000
  PHYB ADDR=0b00001
sheet 14
- USB HUB
- I2C ADDR=0x50
- RESET need to assert
  during 3v3 rise up time to
  meet max Rise time limit
  on 3v3 rail
- NM
- NM
- I2C4_HUB_EEPR_SCL
- HUB_CFG_SEL1
- HUB_CFG_SEL2
- Configuration
- 1
- 0
- 0
- SMBus slave
- The min low pulse
  needed for RESET#
  is 1us
- NM
- 1
- 1
- 0
- EEPROM
- All other configuration
- Internal
- I2C ADDR=0x2C
sheet 15
- USB HOST
- USB OTG
sheet 16
- USB_CONNECTORS/OTG
- USB LED
- Green LED =  LS device attached
  Red LED =  FS device attached
  Orange LED = HS device attached
  LEDs are OFF = No devices are
  attached, or the hub is in
  suspend
- NM
- NM
- NM
- NM
- NM
- NM
- NM
- NM
- SW Note : Need to disable the ports
  6 and 7 by SW configuration
- NM
- OCS[1:7] Contain
  internal pull up to
  3V3 supply
